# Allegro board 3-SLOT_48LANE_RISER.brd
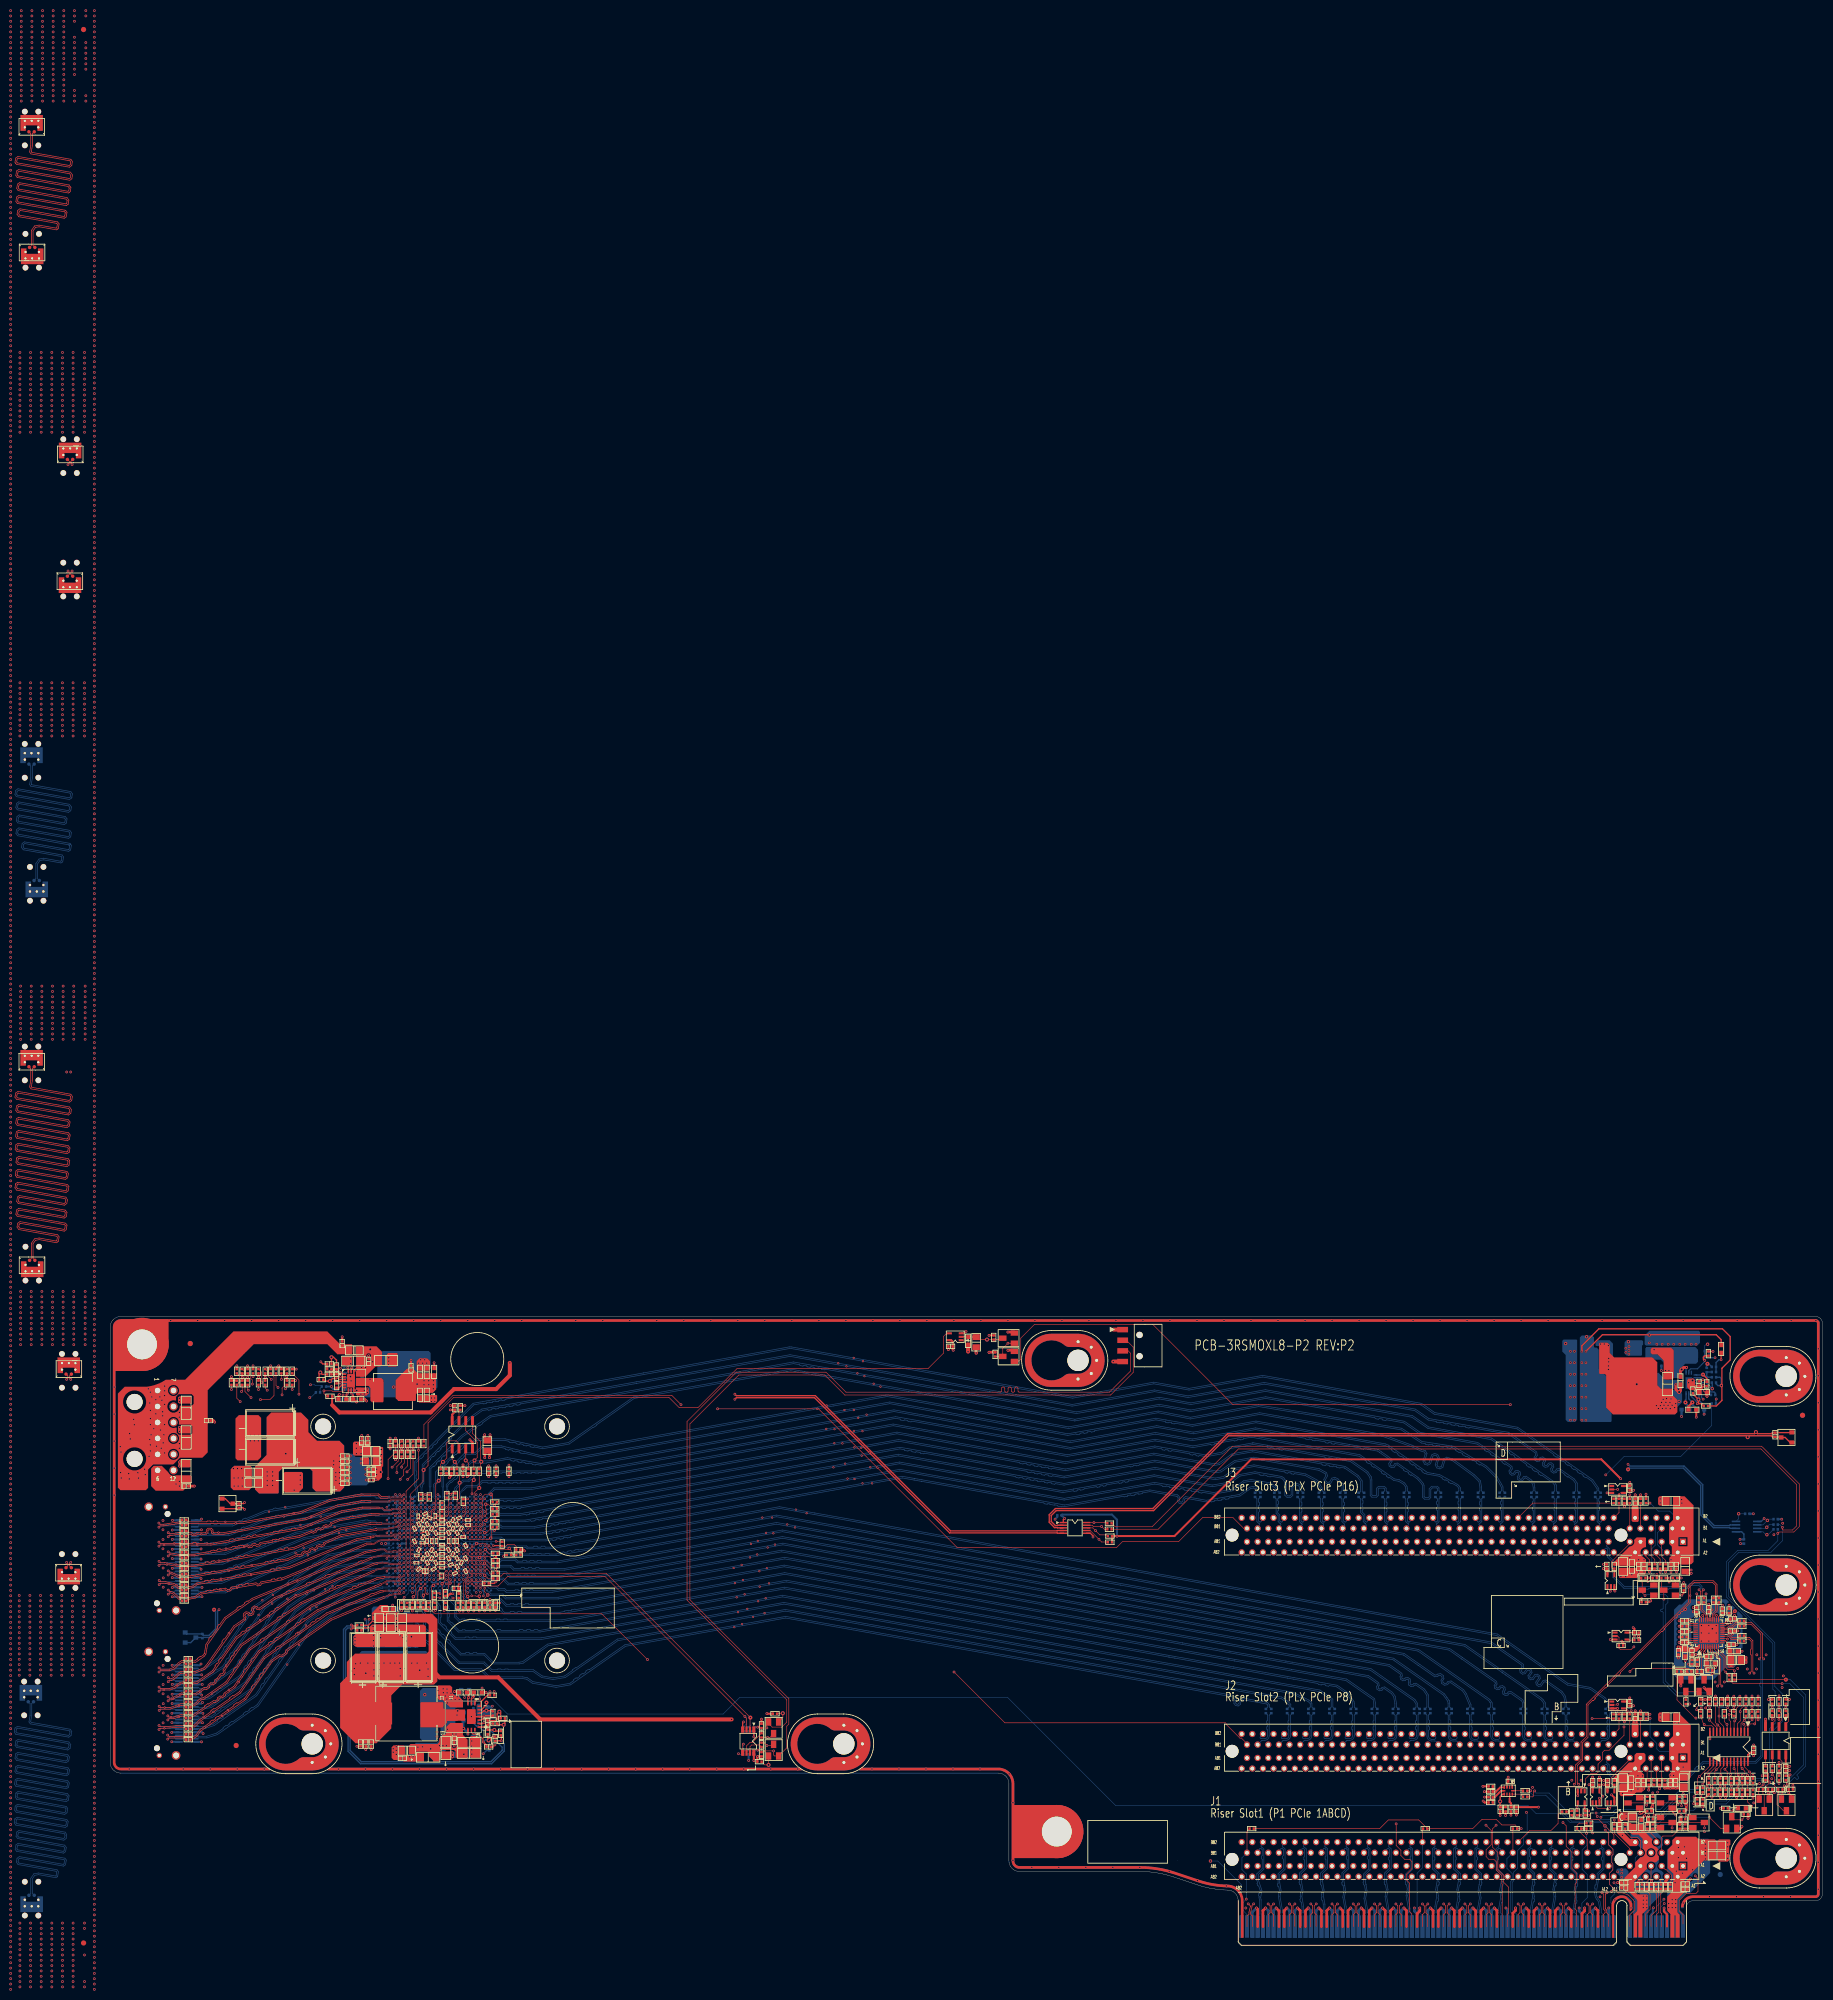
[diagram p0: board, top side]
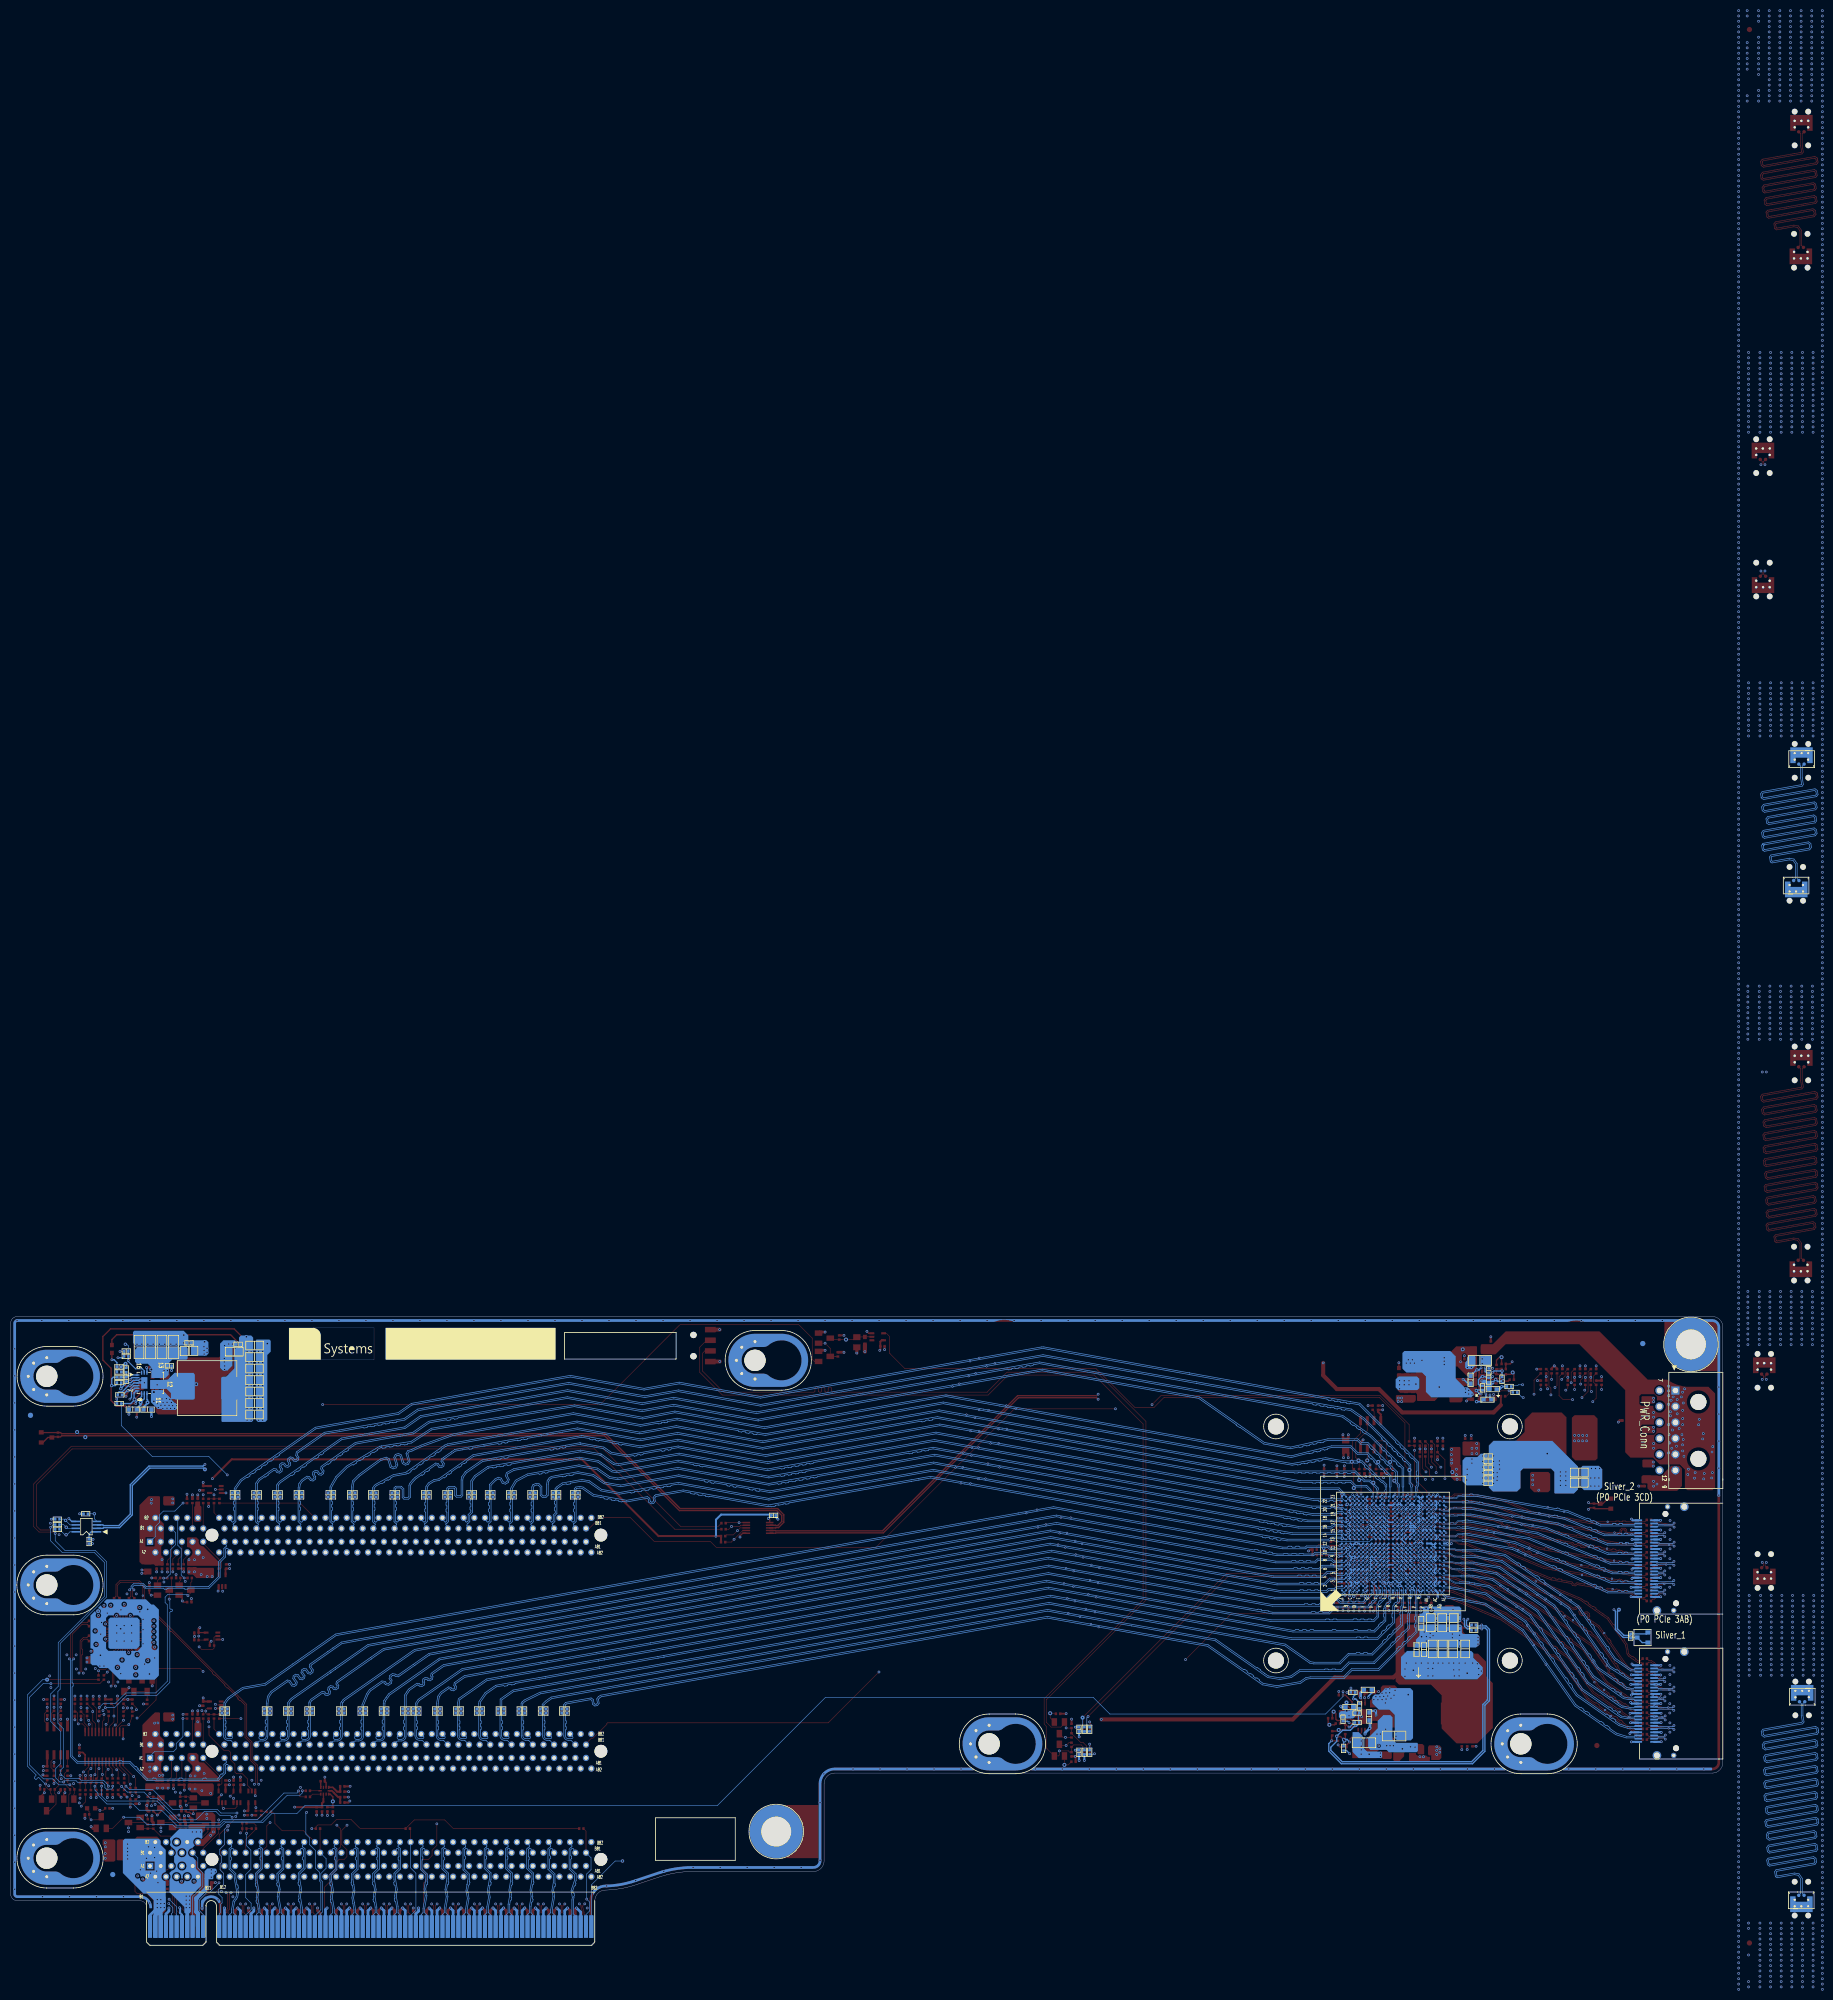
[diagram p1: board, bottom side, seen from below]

Outline 322.05 x 118.24 mm; copper layers: TOP, GND, IN1, VCC, VCC1, IN2, GND1, BOTTOM. Coordinates in mm from the lower left corner of the outline.
Outline path: 0,116.24 0,34.41 0.02,34.15 arc(0.07,33.89) 0.15,33.64 0.27,33.41 0.41,33.19 arc(0.59,32.99) 0.78,32.82 1,32.68 1.23,32.56 1.48,32.48 1.74,32.42 2,32.41 167.05,32.41 167.31,32.39 167.56,32.34 167.81,32.26 168.05,32.14 168.26,31.99 168.46,31.82 168.63,31.63 168.78,31.41 168.89,31.17 168.98,30.93 169.03,30.67 169.05,30.41 169.05,15.91 169.06,15.65 169.11,15.39 169.2,15.14 169.31,14.91 arc(169.46,14.69) 169.63,14.49 169.83,14.32 arc(170.05,14.18) 170.28,14.06 170.53,13.98 170.79,13.92 171.05,13.91 193.68,13.91 194.53,13.89 194.81,13.88 195.38,13.83 195.71,13.8 196.23,13.74 196.58,13.7 197.07,13.62 197.43,13.55 197.91,13.45 198.26,13.37 198.75,13.25 199.09,13.16 199.59,13.01 200,12.88 204.36,11.43 205.18,11.18 206,10.96 206.83,10.78 207.67,10.63 208.51,10.52 209.36,10.45 210.21,10.41 210.49,10.38 arc(210.9,10.27) 211.27,10.07 211.49,9.9 211.69,9.7 211.86,9.47 211.99,9.23 212.09,8.96 212.15,8.69 212.17,8.41 212.17,0.51 212.67,0 282.87,0 283.37,0.51 283.37,7.45 arc(284.33,8.41) 285.28,7.45 285.28,0.51 285.79,0 295.96,0 296.47,0.51 296.47,7.14 arc(296.84,8.04) 297.74,8.41 320.78,8.41 arc(321,8.43) 321.21,8.48 321.41,8.58 321.59,8.7 321.75,8.86 321.88,9.04 arc(321.97,9.24) 322.03,9.46 322.05,9.68 322.05,116.97 322.03,117.2 321.97,117.41 321.88,117.61 321.75,117.79 321.59,117.95 321.41,118.07 321.21,118.17 321,118.23 320.78,118.24 2,118.24 1.74,118.23 1.48,118.18 arc(1.12,118.04) 0.78,117.83 0.59,117.66 0.41,117.46 0.27,117.24 0.15,117.01 0.07,116.76 0.02,116.51 0,116.24

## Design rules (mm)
constraint set DEFAULT: min track width 0.089
net group PWR_VCC: nets P1V8 P3V3
net group VR-G3-VSENSE_S30_VS30: nets P0V9_SENSE_R_N P0V9_SENSE_R_P
net group 50H_W4.5-5.8: nets PEX_EEP_CS_N PEX_EEP_CS_R_N PEX_EEP_SCLK PEX_EEP_SI PEX_EEP_SO PEX_EEP_SO_R RST_PE_SLOT_N RST_PEX_MOS_N
net group CLK-100M_S19-9: nets CLK_100M_PEX8796_DN CLK_100M_PEX8796_DP CLK_100M_PEX8796_R_DN CLK_100M_PEX8796_R_DP CLK_100M_SLOT1_DN CLK_100M_SLOT1_DP CLK_100M_SLOT1_R_DN CLK_100M_SLOT1_R_DP CLK_100M_SLOT2_DN CLK_100M_SLOT2_DP CLK_100M_SLOT2_R_DN CLK_100M_SLOT2_R_DP CLK_100M_SLOT3_DN CLK_100M_SLOT3_DP CLK_100M_SLOT3_R_DN CLK_100M_SLOT3_R_DP
net group DP-85H_W5.3-5.7D6.7-5.3: nets 85OHM_BOT_5INCH_DN 85OHM_BOT_5INCH_DP 85OHM_BOT_10INCH_DN 85OHM_BOT_10INCH_DP 85OHM_L2_5INCH_DN 85OHM_L2_5INCH_DP 85OHM_L2_10INCH_DN 85OHM_L2_10INCH_DP 85OHM_TOP_5INCH_DN 85OHM_TOP_5INCH_DP 85OHM_TOP_10INCH_DN 85OHM_TOP_10INCH_DP PE_SLV_RX_DN<8> PE_SLV_RX_DN<9> PE_SLV_RX_DN<10> PE_SLV_RX_DN<11> PE_SLV_RX_DN<12> PE_SLV_RX_DN<13> PE_SLV_RX_DN<14> PE_SLV_RX_DN<15> PE_SLV_RX_DP<8> PE_SLV_RX_DP<9> PE_SLV_RX_DP<10> PE_SLV_RX_DP<11> PE_SLV_RX_DP<12> PE_SLV_RX_DP<13> PE_SLV_RX_DP<14> PE_SLV_RX_DP<15>
net group JTAG_S10-8_HS-S15-13_VR20/VS30: nets JTAG_R_TCK JTAG_R_TDI JTAG_R_TDO JTAG_R_TMS JTAG_TCK JTAG_TDI JTAG_TDO JTAG_TMS JTAG_TRST_N SLOT2_JTAG_TCK SLOT2_JTAG_TDI SLOT2_JTAG_TDO SLOT2_JTAG_TMS SLOT2_JTAG_TRST_N SLOT3_JTAG_TCK SLOT3_JTAG_TDI SLOT3_JTAG_TDO SLOT3_JTAG_TMS SLOT3_JTAG_TRST_N
net group PCIE-SLOT1-RX_S30-9/S30-15_V9: nets PE_CPU_RX_DN<0> PE_CPU_RX_DN<1> PE_CPU_RX_DN<2> PE_CPU_RX_DN<3> PE_CPU_RX_DN<4> PE_CPU_RX_DN<5> PE_CPU_RX_DN<6> PE_CPU_RX_DN<7> PE_CPU_RX_DN<8> PE_CPU_RX_DN<9> PE_CPU_RX_DN<10> PE_CPU_RX_DN<11> PE_CPU_RX_DN<12> PE_CPU_RX_DN<13> PE_CPU_RX_DN<14> PE_CPU_RX_DN<15> PE_CPU_RX_DP<0> PE_CPU_RX_DP<1> PE_CPU_RX_DP<2> PE_CPU_RX_DP<3> PE_CPU_RX_DP<4> PE_CPU_RX_DP<5> PE_CPU_RX_DP<6> PE_CPU_RX_DP<7> PE_CPU_RX_DP<8> PE_CPU_RX_DP<9> PE_CPU_RX_DP<10> PE_CPU_RX_DP<11> PE_CPU_RX_DP<12> PE_CPU_RX_DP<13> PE_CPU_RX_DP<14> PE_CPU_RX_DP<15> PE_SLOT3_RX_DN<0> PE_SLOT3_RX_DN<1> PE_SLOT3_RX_DN<2> PE_SLOT3_RX_DN<3> PE_SLOT3_RX_DN<4> PE_SLOT3_RX_DN<5> PE_SLOT3_RX_DN<6> PE_SLOT3_RX_DN<7> PE_SLOT3_RX_DN<8> PE_SLOT3_RX_DN<9> PE_SLOT3_RX_DN<10> PE_SLOT3_RX_DN<11> PE_SLOT3_RX_DN<12> PE_SLOT3_RX_DN<13> PE_SLOT3_RX_DN<14> PE_SLOT3_RX_DN<15> PE_SLOT3_RX_DP<0> PE_SLOT3_RX_DP<1> PE_SLOT3_RX_DP<2> PE_SLOT3_RX_DP<3> PE_SLOT3_RX_DP<4> PE_SLOT3_RX_DP<5> PE_SLOT3_RX_DP<6> PE_SLOT3_RX_DP<7> PE_SLOT3_RX_DP<8> PE_SLOT3_RX_DP<9> PE_SLOT3_RX_DP<10> PE_SLOT3_RX_DP<11> PE_SLOT3_RX_DP<12> PE_SLOT3_RX_DP<13> PE_SLOT3_RX_DP<14> PE_SLOT3_RX_DP<15>
net group PCIE-SLOT1-TX_S30-9/S30-15_V9: nets PE_CPU_TX_DN<0> PE_CPU_TX_DN<1> PE_CPU_TX_DN<2> PE_CPU_TX_DN<3> PE_CPU_TX_DN<4> PE_CPU_TX_DN<5> PE_CPU_TX_DN<6> PE_CPU_TX_DN<7> PE_CPU_TX_DN<8> PE_CPU_TX_DN<9> PE_CPU_TX_DN<10> PE_CPU_TX_DP<0> PE_CPU_TX_DP<1> PE_CPU_TX_DP<2> PE_CPU_TX_DP<3> PE_CPU_TX_DP<4> PE_CPU_TX_DP<5> PE_CPU_TX_DP<6> PE_CPU_TX_DP<7> PE_CPU_TX_DP<8> PE_CPU_TX_DP<9> PE_CPU_TX_DP<10> PE_CPU_TX_DP<15> PE_SLOT3_TX_C_DN<0> PE_SLOT3_TX_C_DN<1> PE_SLOT3_TX_C_DN<2> PE_SLOT3_TX_C_DN<3> PE_SLOT3_TX_C_DN<4> PE_SLOT3_TX_C_DN<5> PE_SLOT3_TX_C_DN<6> PE_SLOT3_TX_C_DN<7> PE_SLOT3_TX_C_DN<8> PE_SLOT3_TX_C_DN<9> PE_SLOT3_TX_C_DN<10> PE_SLOT3_TX_C_DN<11> PE_SLOT3_TX_C_DN<12> PE_SLOT3_TX_C_DN<13> PE_SLOT3_TX_C_DN<14> PE_SLOT3_TX_C_DN<15> PE_SLOT3_TX_C_DP<0> PE_SLOT3_TX_C_DP<1> PE_SLOT3_TX_C_DP<2> PE_SLOT3_TX_C_DP<3> PE_SLOT3_TX_C_DP<4> PE_SLOT3_TX_C_DP<5> PE_SLOT3_TX_C_DP<6> PE_SLOT3_TX_C_DP<7> PE_SLOT3_TX_C_DP<8> PE_SLOT3_TX_C_DP<9> PE_SLOT3_TX_C_DP<10> PE_SLOT3_TX_C_DP<11> PE_SLOT3_TX_C_DP<12> PE_SLOT3_TX_C_DP<13> PE_SLOT3_TX_C_DP<14> PE_SLOT3_TX_C_DP<15> PE_SLOT3_TX_DN<0> PE_SLOT3_TX_DN<1> PE_SLOT3_TX_DN<2> PE_SLOT3_TX_DN<3> PE_SLOT3_TX_DN<4> PE_SLOT3_TX_DN<5> PE_SLOT3_TX_DN<6> PE_SLOT3_TX_DN<7> PE_SLOT3_TX_DN<8> PE_SLOT3_TX_DN<9> PE_SLOT3_TX_DN<10> PE_SLOT3_TX_DN<11> PE_SLOT3_TX_DN<12> PE_SLOT3_TX_DN<13> PE_SLOT3_TX_DN<14> PE_SLOT3_TX_DN<15> PE_SLOT3_TX_DP<0> PE_SLOT3_TX_DP<1> PE_SLOT3_TX_DP<2> PE_SLOT3_TX_DP<3> PE_SLOT3_TX_DP<4> PE_SLOT3_TX_DP<5> PE_SLOT3_TX_DP<6> PE_SLOT3_TX_DP<7> PE_SLOT3_TX_DP<8> PE_SLOT3_TX_DP<9> PE_SLOT3_TX_DP<10> PE_SLOT3_TX_DP<11> PE_SLOT3_TX_DP<12> PE_SLOT3_TX_DP<13> PE_SLOT3_TX_DP<14> PE_SLOT3_TX_DP<15>
net group PCIE-SLOT2-RX_S30-9/S30-15_V9: nets PE_SLOT2_RX_DN<0> PE_SLOT2_RX_DN<1> PE_SLOT2_RX_DN<2> PE_SLOT2_RX_DN<3> PE_SLOT2_RX_DN<4> PE_SLOT2_RX_DN<5> PE_SLOT2_RX_DN<6> PE_SLOT2_RX_DN<7> PE_SLOT2_RX_DN<8> PE_SLOT2_RX_DN<9> PE_SLOT2_RX_DN<10> PE_SLOT2_RX_DN<11> PE_SLOT2_RX_DN<12> PE_SLOT2_RX_DN<13> PE_SLOT2_RX_DN<14> PE_SLOT2_RX_DN<15> PE_SLOT2_RX_DP<0> PE_SLOT2_RX_DP<1> PE_SLOT2_RX_DP<2> PE_SLOT2_RX_DP<3> PE_SLOT2_RX_DP<4> PE_SLOT2_RX_DP<5> PE_SLOT2_RX_DP<6> PE_SLOT2_RX_DP<7> PE_SLOT2_RX_DP<8> PE_SLOT2_RX_DP<9> PE_SLOT2_RX_DP<10> PE_SLOT2_RX_DP<11> PE_SLOT2_RX_DP<12> PE_SLOT2_RX_DP<13> PE_SLOT2_RX_DP<14> PE_SLOT2_RX_DP<15>
net group PCIE-SLOT2-TX_S30-9/S30-15_V9: nets PE_SLOT2_TX_C_DN<0> PE_SLOT2_TX_C_DN<1> PE_SLOT2_TX_C_DN<2> PE_SLOT2_TX_C_DN<3> PE_SLOT2_TX_C_DN<4> PE_SLOT2_TX_C_DN<5> PE_SLOT2_TX_C_DN<6> PE_SLOT2_TX_C_DN<7> PE_SLOT2_TX_C_DN<8> PE_SLOT2_TX_C_DN<9> PE_SLOT2_TX_C_DN<10> PE_SLOT2_TX_C_DN<11> PE_SLOT2_TX_C_DN<12> PE_SLOT2_TX_C_DN<13> PE_SLOT2_TX_C_DN<14> PE_SLOT2_TX_C_DN<15> PE_SLOT2_TX_C_DP<0> PE_SLOT2_TX_C_DP<1> PE_SLOT2_TX_C_DP<2> PE_SLOT2_TX_C_DP<3> PE_SLOT2_TX_C_DP<4> PE_SLOT2_TX_C_DP<5> PE_SLOT2_TX_C_DP<6> PE_SLOT2_TX_C_DP<7> PE_SLOT2_TX_C_DP<8> PE_SLOT2_TX_C_DP<9> PE_SLOT2_TX_C_DP<10> PE_SLOT2_TX_C_DP<11> PE_SLOT2_TX_C_DP<12> PE_SLOT2_TX_C_DP<13> PE_SLOT2_TX_C_DP<14> PE_SLOT2_TX_C_DP<15> PE_SLOT2_TX_DN<0> PE_SLOT2_TX_DN<1> PE_SLOT2_TX_DN<2> PE_SLOT2_TX_DN<3> PE_SLOT2_TX_DN<4> PE_SLOT2_TX_DN<5> PE_SLOT2_TX_DN<6> PE_SLOT2_TX_DN<7> PE_SLOT2_TX_DN<8> PE_SLOT2_TX_DN<9> PE_SLOT2_TX_DN<10> PE_SLOT2_TX_DN<11> PE_SLOT2_TX_DN<12> PE_SLOT2_TX_DN<13> PE_SLOT2_TX_DN<14> PE_SLOT2_TX_DN<15> PE_SLOT2_TX_DP<0> PE_SLOT2_TX_DP<1> PE_SLOT2_TX_DP<2> PE_SLOT2_TX_DP<3> PE_SLOT2_TX_DP<4> PE_SLOT2_TX_DP<5> PE_SLOT2_TX_DP<6> PE_SLOT2_TX_DP<7> PE_SLOT2_TX_DP<8> PE_SLOT2_TX_DP<9> PE_SLOT2_TX_DP<10> PE_SLOT2_TX_DP<11> PE_SLOT2_TX_DP<12> PE_SLOT2_TX_DP<13> PE_SLOT2_TX_DP<14> PE_SLOT2_TX_DP<15>
net group PE_J7-J8_TX: nets PE_SLV_TX_DN<0> PE_SLV_TX_DN<1> PE_SLV_TX_DN<2> PE_SLV_TX_DN<3> PE_SLV_TX_DN<4> PE_SLV_TX_DN<5> PE_SLV_TX_DN<6> PE_SLV_TX_DN<7> PE_SLV_TX_DP<0> PE_SLV_TX_DP<1> PE_SLV_TX_DP<2> PE_SLV_TX_DP<3> PE_SLV_TX_DP<4> PE_SLV_TX_DP<5> PE_SLV_TX_DP<6> PE_SLV_TX_DP<7> PE_SLV_TX_DP<15>
net group PWR2: nets GND
net group PWR-20: nets VR_P0V9_BT VR_P1V8_BT VR_P3V3_BT
net group PWR_S10: nets CLK_BUF_HIBW_BYPM_LOBW_N I2C_SC6_2N7002_G_SCL I2C_SD6_2N7002_G_SDA I2C_SLOT2_2N7002_G_SCL I2C_SLOT2_2N7002_G_SDA I2C_SLOT3_2N7002_G_SCL I2C_SLOT3_2N7002_G_SDA P0V9_VREF P1V8_FB P1V8_FB_RC P3V3_FB P3V3_FB_RC P3V3_RT P12V P12V_MB P12V_PSU
net group PWR_W30: nets P0V9 P0V9_A P0V9_RT P0V9_VCC P0V9_VIN P1V8_A P1V8_AGND P1V8_RT P1V8_SS P1V8_VCC P1V8_VIN P3V3_AGND P3V3_BUF_VDDA P3V3_BUF_VDDR P3V3_CLK_BUF_VDD P3V3_MB P3V3_STBY_MB P3V3_VCC P3V3_VIN VR_P0V9_SW VR_P1V8_PVIN VR_P3V3_SW
net group RESET_S10-8_HS-S15-13_VR20/VS30: nets P3V3_PG
net group SMB-50H_W4.5-5.8: nets I2C_PCA9548_SC3_SLOT2_SCL I2C_PCA9548_SC5_3V3_PE_SCL I2C_PCA9548_SC5_P1V8_SCL I2C_PCA9548_SC5_PE_SCL I2C_PCA9548_SC6_3V3_CLK_SCL I2C_PCA9548_SC6_CLK_SCL I2C_PCA9548_SD3_SLOT2_SDA I2C_PCA9548_SD5_3V3_PE_SDA I2C_PCA9548_SD5_P1V8_SDA I2C_PCA9548_SD5_PE_SDA I2C_PCA9548_SD6_3V3_CLK_SDA I2C_PCA9548_SD6_CLK_SDA I2C_PE_SCL_R I2C_PE_SDA_R I2C_SC5_2N7002_G_SCL I2C_SD5_2N7002_G_SDA I2C_SLOT1_2N7002_G_SCL I2C_SLOT1_2N7002_G_SDA I2C_SLOT1_3V3_SCL I2C_SLOT1_3V3_SDA I2C_SLOT2_3V3_SCL I2C_SLOT2_3V3_SDA I2C_SLOT3_3V3_SCL I2C_SLOT3_3V3_SDA
net group SPI: nets PEX_EEP_HOLD_N
net group VR-G2-VCC_S20V20/S30_VS30: nets VR_P3V3_PVIN
net group VR-NOISY_S20/S30_VS30: nets VR_P1V8_SW
net group VR-SEN-S5/30: nets P0V9_AGND P0V9_COMP P0V9_COMP_RC P0V9_FB P0V9_FB_RC P0V9_VSNS P1V8_COMP P1V8_COMP_RC P1V8_VSENSE_R P3V3_COMP P3V3_COMP_RC P3V3_SENSE_R P3V3_VREF P3V3_VSNS
net group VR_SEN: nets THER_SEN1_DN_1 THER_SEN1_DN_2 THER_SEN1_DP_1 THER_SEN1_DP_2 THER_SEN2_DN THER_SEN2_DP

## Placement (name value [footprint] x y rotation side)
C1  -  [C0402]  64.85 101.09 90 top
C2  -  [C0201]  57.25 78.37 112.5 top
C3  -  [C0402]  66.37 89.15 90 top
C4  -  [C0201]  57.25 75.97 112.5 top
C5  -  [C0201]  59.25 81.16 22.5 top
C6  -  [C0201]  58.05 74.37 247.5 top
C7  -  [C0201]  58.85 78.37 67.5 top
C8  -  [C0402]  72.59 89.15 90 top
C9  -  [C0201]  59.65 79.17 292.5 top
C10  -  [C0201]  65.25 72.76 112.5 top
C11  -  [C0402]  44.15 89.92 0 top
C12  -  [C0402]  75.01 89.15 90 top
C13  -  [C0402]  44.15 88.9 0 top
C14  -  [C0201]  65.25 74.36 112.5 top
C15  -  [C0201]  58.85 72.76 67.5 top
C16  -  [C0201]  62.45 79.17 180 top
C17  -  [C0201]  58.05 79.16 112.5 top
C18  -  [C0201]  64.46 73.56 247.5 top
C19  -  [C0201]  66.06 71.96 247.5 top
C20  -  [C0201]  64.45 78.37 67.5 top
C21  -  [C0201]  66.86 72.77 292.5 top
C22  -  [C0201]  61.25 79.17 292.5 top
C23  -  [C0402]  14.68 38.69 180 top
C24  -  [C0402]  14.68 40.72 180 top
C25  -  [C0402]  14.68 42.75 180 top
C26  -  [C0402]  14.68 44.78 180 top
C27  -  [C0402]  281.26 44.07 270 bottom
C28  -  [C0402]  273.3 44.07 270 bottom
C29  -  [C0402]  269.3 44.07 270 bottom
C30  -  [C0402]  265.3 44.07 270 bottom
C31  -  [C0402]  282.28 44.07 270 bottom
C32  -  [C0402]  274.31 44.07 270 bottom
C33  -  [C0402]  270.31 44.07 270 bottom
C34  -  [C0402]  266.31 44.07 270 bottom
C35  -  [C0402]  14.68 39.7 180 top
C36  -  [C0402]  14.68 41.74 180 top
C37  -  [C0402]  14.68 43.77 180 top
C38  -  [C0402]  14.68 45.8 180 top
C39  -  [C0402]  280.34 84.71 270 bottom
C40  -  [C0402]  276.3 84.71 270 bottom
C41  -  [C0402]  272.37 84.71 270 bottom
C42  -  [C0402]  268.33 84.71 270 bottom
C43  -  [C0402]  279.33 84.71 270 bottom
C44  -  [C0402]  275.29 84.71 270 bottom
C45  -  [C0402]  271.35 84.71 270 bottom
C46  -  [C0402]  267.31 84.71 270 bottom
C47  -  [C0805]  49.1 91.06 180 top
C48  -  [C0805]  70.94 93.98 90 top
C49  -  [C0402]  49.1 89.53 180 top
C50  -  [C0402]  47.32 94.87 90 top
C51  -  [C0402]  49.1 88.52 180 top
C52  -  [C0402]  48.46 94.87 90 top
C53  -  [C0201#2]  62.33 69.44 270 top
C54  -  [C0201#2]  49.1 87.5 180 top
C55  -  [C0402]  259.3 44.07 270 bottom
C56  -  [C0402]  255.3 44.07 270 bottom
C57  -  [C0402]  251.3 44.07 270 bottom
C58  -  [C0402]  247.3 44.07 270 bottom
C59  -  [C0402]  245.26 44.07 270 bottom
C60  -  [C0402]  241.28 44.07 270 bottom
C61  -  [C0402]  237.31 44.07 270 bottom
C62  -  [C0402]  233.35 44.07 270 bottom
C63  -  [C0402]  229.31 44.07 270 bottom
C64  -  [C0402]  225.38 44.07 270 bottom
C65  -  [C0402]  221.38 44.07 270 bottom
C66  -  [C0402]  217.38 44.07 270 bottom
C67  -  [C0402]  260.31 44.07 270 bottom
C68  -  [C0402]  256.31 44.07 270 bottom
C69  -  [C0402]  252.31 44.07 270 bottom
C70  -  [C0402]  248.31 44.07 270 bottom
C71  -  [C0402]  246.28 44.07 270 bottom
C72  -  [C0402]  242.29 44.07 270 bottom
C73  -  [C0402]  238.33 44.07 270 bottom
C74  -  [C0402]  234.37 44.07 270 bottom
C75  -  [C0402]  230.33 44.07 270 bottom
C76  -  [C0402]  226.39 44.07 270 bottom
C77  -  [C0402]  222.39 44.07 270 bottom
C78  -  [C0402]  218.39 44.07 270 bottom
C79  -  [C0402]  14.68 46.82 180 top
C80  -  [C0402]  14.68 48.85 180 top
C81  -  [C0402]  14.68 50.88 180 top
C82  -  [C0402]  14.68 52.91 180 top
C83  -  [C0402]  13.92 64.76 180 top
C84  -  [C0402]  13.92 66.8 180 top
C85  -  [C0402]  13.92 68.83 180 top
C86  -  [C0402]  13.92 70.86 180 top
C87  -  [C0402]  13.92 72.89 180 top
C88  -  [C0402]  13.92 74.92 180 top
C89  -  [C0402]  13.92 76.96 180 top
C90  -  [C0402]  13.92 78.99 180 top
C91  -  [C0402]  14.68 47.83 180 top
C92  -  [C0402]  14.68 49.86 180 top
C93  -  [C0402]  14.68 51.9 180 top
C94  -  [C0402]  14.68 53.93 180 top
C95  -  [C0402]  13.92 65.78 180 top
C96  -  [C0402]  13.92 67.81 180 top
C97  -  [C0402]  13.92 69.84 180 top
C98  -  [C0402]  13.92 71.88 180 top
C99  -  [C0402]  13.92 73.91 180 top
C100  -  [C0402]  13.92 75.94 180 top
C101  -  [C0402]  13.92 77.97 180 top
C102  -  [C0402]  13.92 80 180 top
C103  -  [C0402]  262.33 84.71 270 bottom
C104  -  [C0402]  258.29 84.71 270 bottom
C105  -  [C0402]  254.33 84.71 270 bottom
C106  -  [C0402]  250.29 84.71 270 bottom
C107  -  [C0402]  244.36 84.71 270 bottom
C108  -  [C0402]  240.36 84.71 270 bottom
C109  -  [C0402]  235.85 84.71 270 bottom
C110  -  [C0402]  232.36 84.71 270 bottom
C111  -  [C0402]  228.36 84.71 270 bottom
C112  -  [C0402]  224.36 84.71 270 bottom
C113  -  [C0402]  219.98 84.71 270 bottom
C114  -  [C0402]  216.36 84.71 270 bottom
C115  -  [C0402]  261.32 84.71 270 bottom
C116  -  [C0402]  257.28 84.71 270 bottom
C117  -  [C0402]  253.32 84.71 270 bottom
C118  -  [C0402]  249.28 84.71 270 bottom
C119  -  [C0402]  243.34 84.71 270 bottom
C120  -  [C0402]  239.34 84.71 270 bottom
C121  -  [C0402]  234.84 84.71 270 bottom
C122  -  [C0402]  231.34 84.71 270 bottom
C123  -  [C0402]  227.34 84.71 270 bottom
C124  -  [C0402]  223.34 84.71 270 bottom
C125  -  [C0402]  218.96 84.71 270 bottom
C126  -  [C0402]  215.34 84.71 270 bottom
C127  -  [C0402]  52.66 94.36 270 top
C128  -  [C0201]  58.05 70.77 225 top
C129  -  [C0201]  58.73 75.74 0 top
C130  -  [C0201]  57.66 73.33 180 top
C131  -  [C0201]  61.16 80.77 270 top
C132  -  [C0201]  64.05 71.56 22.5 top
C133  -  [C0201]  65.26 71.17 292.5 top
C134  -  [C0201]  58.85 76.77 67.5 top
C135  -  [C0201]  58.96 70.36 270 top
C136  -  [C0201]  60.05 80.36 157.5 top
C137  -  [C0201]  65.65 80.36 22.5 top
C138  -  [C0201]  64.45 79.97 67.5 top
C139  -  [C0201]  58.85 79.97 247.5 top
C140  -  [C0201]  65.25 77.56 112.5 top
C141  -  [C0201]  66.86 75.17 292.5 top
C142  -  [C0201]  64.86 69.96 202.5 top
C143  -  [C0201]  66.4 76.77 0 top
C144  -  [C0201]  65.26 79.17 292.5 top
C145  -  [C0402]  71.45 64.01 270 top
C146  -  [C0201]  66.05 78.37 67.5 top
C147  -  [C0402]  72.47 64.01 270 top
C148  -  [C0201]  66.86 70.37 292.5 top
C149  -  [C0402]  44.15 91.01 0 top
C150  -  [C0201]  57.61 71.96 180 top
C151  -  [C0201]  67.32 80 0 top
C152  -  [C0805]  295.99 30.61 270 top
C153  -  [C0402]  293.45 30.61 270 top
C154  -  [C0402]  294.46 30.61 270 top
C155  -  [C0603]  286.08 30.61 270 top
C156  -  [C0402]  287.35 30.61 270 top
C157  -  [C0402]  288.37 30.61 270 top
C158  -  [C0402]  286.84 43.05 90 top
C159  -  [C0402]  277.45 24.89 270 top
C160  -  [C0402]  71.2 89.15 90 top
C161  -  [C0201]  67.34 79.04 0 top
C162  -  [C0201]  57.95 80.67 270 top
C163  -  [C0201]  62.45 71.04 180 top
C164  -  [C0201]  60.85 70.76 208.4 top
C165  -  [TAJ_D_7-3X4-3]  52.88 54.2 90 top
C166  -  [TAJ_D_7-3X4-3]  30.05 98.17 180 top
C167  -  [TAJ_D_7-3X4-3]  30.05 92.84 180 top
C168  -  [C0805]  302.21 18.8 0 top
C169  -  [C0805]  286.34 23.24 90 top
C170  -  [TAJ_D_7-3X4-3]  58.12 54.23 90 top
C171  -  [TAJ_D_7-3X4-3]  37.03 87.38 180 top
C172  -  [C0402]  278.84 30.61 90 top
C173  -  [TAJ_D_7-3X4-3]  47.68 54.2 90 top
C174  -  [C0402]  47.09 37.85 270 top
C175  -  [C0402]  44.15 86.87 0 bottom
C176  -  [C0402]  48.08 37.85 270 top
C177  -  [C0402]  44.15 86.87 0 top
C178  -  [C0402]  263.48 25.6 270 top
C179  -  [C0402]  264.49 25.6 270 top
C180  -  [C0402]  261.44 25.6 270 top
C181  -  [C0201]  65.28 76.02 90 top
C182  -  [C0402]  44.15 87.88 0 bottom
C183  -  [C0402]  44.15 89.92 0 bottom
C184  -  [C0402]  44.15 87.88 0 top
C185  -  [C0402]  44.15 91.01 0 bottom
C186  -  [C0402]  44.15 88.9 0 bottom
C187  -  [C0402]  44.15 92.02 0 bottom
C188  -  [C0402]  44.15 92.02 0 top
C189  -  [C0402]  259.67 27.89 180 top
C190  -  [C0402]  259.67 28.91 180 top
C191  -  [C0402]  158.07 112.65 180 top
C192  -  [C0603]  161.37 113.67 270 top
C193  -  [C0805]  162.89 113.41 270 top
C194  -  [C0201]  59.54 70.36 270 top
C215  -  [C0603]  305.39 55.32 0 top
C216  -  [C0402]  296.12 59 180 top
C217  -  [C0402]  304.88 56.59 0 top
C218  -  [C0402]  300.68 63.12 90 top
C219  -  [C0402]  298.42 63.12 90 top
C220  -  [C0402]  296.12 56.97 180 top
C221  -  [C0402]  296.12 61.03 180 top
C222  -  [C0402]  303.22 62.87 90 top
C223  -  [C0402]  309.12 36.68 90 top
C224  -  [C0603]  296.25 55.07 270 top
C225  -  [C0402]  297.52 55.07 270 top
C226  -  [C0603]  301.07 53.03 0 top
C227  -  [C0402]  300.69 54.3 0 top
C242  -  [C0805]  296.24 71.25 270 top
C243  -  [C0402]  294.59 71.25 270 top
C244  -  [C0402]  293.57 71.25 270 top
C245  -  [C0603]  286.21 71.25 270 top
C246  -  [C0402]  288.49 71.25 270 top
C247  -  [C0402]  287.48 71.25 270 top
C248  -  [C0402]  286.84 83.57 90 top
C249  -  [C0805]  302.21 16.89 0 top
C250  -  [C0402]  296.24 11.56 0 top
C251  -  [C0402]  296.24 10.54 0 top
C252  -  [C0603]  287.99 22.86 90 top
C253  -  [C0402]  284.68 10.79 180 top
C254  -  [C0402]  284.68 11.81 180 top
C255  -  [C0402]  283.92 22.35 90 top
C257  -  [C0402]  305.14 61.39 0 top
C258  -  [C0402]  305.14 59.13 0 top
C259  -  [C0402]  307.29 75.95 270 bottom
C260  -  [C0402]  17.35 58.17 90 bottom
C265  -  [C0402]  178.54 80.87 180 bottom
C269  -  [C0201]  61.25 77.57 292.5 top
C271  -  [C0201]  61.25 73.57 292.5 top
C273  -  [C0201]  61.25 71.97 292.5 top
C275  -  [C0201]  63.66 77.57 292.5 top
C277  -  [C0201]  63.65 72.76 112.5 top
C279  -  [C0201]  60.45 74.36 67.5 top
C281  -  [C0201]  60.45 72.76 67.5 top
C283  -  [C0201]  62.45 77.44 180 top
C287  -  [C0201]  62.45 71.91 180 top
C290  -  [C0201]  62.45 72.77 0 top
C294  -  [C0201]  62.45 74.5 0 top
C297  -  [C0201]  62.45 73.63 180 top
C352  -  [C0402]  287.1 58.8 0 top
C386  -  [C0201]  59.65 71.96 292.5 top
C390  -  [C0201]  59.65 77.57 292.5 top
C394  -  [C0201]  62.45 75.36 180 top
C398  -  [C0201]  60.45 78.37 67.5 top
C402  -  [C0201]  62.45 76.58 0 top
C406  -  [C0201]  62.45 80.01 180 top
C410  -  [C0201]  62.45 78.31 0 top
C414  -  [C0201]  64.55 76.02 90 top
C418  -  [C0201]  63.65 74.36 112.5 top
C422  -  [C0201]  59.6 76.02 270 top
C426  -  [C0201]  60.49 76.02 90 top
C430  -  [C0201]  61.38 76.02 270 top
C434  -  [C0201]  63.67 76.02 270 top
C438  -  [C0201]  63.66 79.17 292.5 top
C442  -  [C0201]  59.65 73.57 292.5 top
C450  -  [C0402]  121.11 36.32 90 bottom
C451  -  [C0402]  121.11 40.64 90 bottom
C452  -  [C0402]  315.16 33.27 270 top
C455  -  [C0402]  281.51 71.25 90 top
C456  -  [C0402]  281.64 30.61 90 top
C460  -  [C0402]  285.83 85.98 270 top
C461  -  [C0402]  285.83 45.47 270 top
C463  -  [C1206]  14.3 101.09 90 top
C464  -  [C1206]  14.3 95.5 90 top
C465  -  [C0402]  18.49 98.68 0 top
C466  -  [C1206]  14.3 89.15 90 top
C467  -  [C0402]  14.3 86.36 0 top
C468  -  [C0402]  313.13 96.01 90 top
C469  -  [C0402]  24.23 82.68 270 top
C477  -  [C0805]  293.57 83.57 180 top
C478  -  [C0805]  284.56 71.25 270 top
C479  -  [C0805]  293.57 42.93 180 top
C480  -  [C0805]  284.56 30.61 270 top
CON1  -  [HEADER1X4S2NH_P2H2_RA]  193.63 112.78 270 top
D1  -  [LED0603]  306.91 25.78 0 top
H1  -  [HOLE_C10D5-6B10_NPB_H11_STANDOFF]  6 113 180 bottom
J1  -  [PCIE_X16D_H11]  295.83 14.93 270 top
J2  -  [PCIE_X16D_H11]  295.83 35.25 270 top
J3  -  [PCIE_X16D_H11]  295.83 75.89 270 top
J5  -  [GF_PCIE_X16]  284.33 7.45 180 bottom
J6  -  [PWR2X6D2NH_P3W3H8-9_RA]  8.92 104.32 90 bottom
J7  -  [SLIVER_X8_RA]  7.84 45.5 90 bottom
J8  -  [SLIVER_X8_RA]  7.84 72.75 90 bottom
L1  -  [B2012]  305.77 53.67 0 top
L2  -  [B2012]  49.1 92.96 180 top
L3  -  [B2012]  27 88.9 0 top
L4  -  [B2012]  27 87 0 top
L5  -  [B2012]  27 87 0 bottom
L6  -  [B2012]  27 88.9 0 bottom
ME1  -  [LABEL20X4_SST21X5]  217.88 110.24 180 bottom
ME4  -  [LABEL_32X6_FULL]  251.54 110.11 180 bottom
ME5  -  [ZT_LOG_6X16]  269.7 110.11 180 bottom
MH1  -  [HOLE_D3N_PKO10]  40.05 53.56 0 top
MH2  -  [HOLE_D3N_PKO10]  84.06 53.56 0 top
MH3  -  [HOLE_D3N_PKO10]  84.05 97.57 0 top
MH4  -  [HOLE_D3N_PKO10]  40.05 97.57 0 top
MH5  -  [GND_C10D4_6-5B10_OB5]  138 37.9 270 top
MH6  -  [GND_C10D4_6-5B10_OB5]  315.25 16.41 270 top
MH7  -  [GND_C10D4_6-5B10_OB5]  315.25 67.77 270 top
MH8  -  [HOLE_C10D5-6B10_NPB_H11_STANDOFF]  178.05 21.41 180 bottom
MH9  -  [GND_C10D4_6-5B10_OB5]  182.05 110 270 top
MH10  -  [GND_C10D4_6-5B10_OB5]  38 37.9 270 top
MH11  -  [GND_C10D4_6-5B10_OB5]  315.25 107 270 top
NOREF  -  []  10.85 42.78 90 top
NOREF#2  -  []  9.2 51.79 90 top
NOREF#3  -  []  278.33 7.8 0 top
NOREF#4  -  [unnamed#2]  -5 360.19 0 top
NOREF#5  -  []  234.32 7.8 0 top
NOREF#6  -  []  10.92 66.43 90 top
NOREF#7  -  [unnamed#2]  23.7 37.59 0 top
NOREF#8  -  []  299.29 66.86 0 top
NOREF#9  -  []  9.2 71.84 90 top
NOREF#10  -  []  238.33 7.8 0 top
NOREF#11  -  []  10.92 70.03 90 top
NOREF#12  -  []  226.34 7.8 0 top
NOREF#13  -  []  10.92 49.97 90 top
NOREF#14  -  []  214.61 7.8 0 top
NOREF#15  -  []  230.33 7.8 0 top
NOREF#16  -  []  273.33 7.8 0 top
NOREF#17  -  []  275.79 30.3 180 top
NOREF#18  -  []  10.92 73.61 90 top
NOREF#19  -  []  9.22 68.23 90 top
NOREF#20  -  [unnamed#2]  318.31 99.67 0 top
NOREF#21  -  []  10.9 46.36 90 top
NOREF#22  -  []  269.34 7.8 0 top
NOREF#23  -  []  251.33 7.8 0 top
NOREF#24  -  []  9.2 48.19 90 top
NOREF#25  -  []  259.34 7.8 0 top
NOREF#26  -  [unnamed#2]  15.06 113.16 0 top
NOREF#27  -  []  247.32 7.8 0 top
NOREF#28  -  []  218.31 7.8 0 top
NOREF#29  -  []  10.92 77.22 90 top
NOREF#30  -  []  265.33 7.8 0 top
NOREF#31  -  []  9.22 44.58 90 top
NOREF#32  -  []  9.17 75.44 90 top
NOREF#33  -  []  9.17 79.02 90 top
NOREF#34  -  []  9.2 40.97 90 top
NOREF#35  -  []  302.74 48.77 180 top
NOREF#36  -  []  10.82 39.17 90 top
NOREF#37  -  []  222.33 7.8 0 top
NOREF#38  -  []  255.32 7.8 0 top
NOREF#39  -  []  308.79 51.21 180 top
NOREF#40  -  []  310.59 53.87 180 top
NOREF#41  -  [unnamed#2]  -5 0.47 0 top
NOREF#42  -  [unnamed#2]  183.9 15.47 0 top
NOREF#43  -  []  18.67 -76.43 0 top
NOREF#44  -  []  242.34 7.8 0 top
NOREF#45  -  [unnamed#2]  302.85 13.34 180 bottom
NOREF#46  -  [unnamed#2]  15.06 113.16 180 bottom
NOREF#47  -  [unnamed#2]  318.31 99.67 180 bottom
NOREF#48  -  [unnamed#2]  200.74 16 180 bottom
PC506  -  [C0402]  300.31 111.74 0 bottom
PC508  -  [C0603]  296.3 100.75 0 bottom
PC509  -  [C0402]  298.84 105.65 270 top
PC510  -  [C0603]  299.07 100.75 0 bottom
PC511  -  [C0402]  292.18 108.97 180 bottom
PC514  -  [C0603]  295.36 106.18 270 top
PC515  -  [C1206]  293.57 112.52 90 bottom
PC516  -  [C0402]  300.3 106.43 90 bottom
PC517  -  [C1206]  292.94 105.54 270 top
PC518  -  [C0402]  301.66 106.82 180 bottom
PC519  -  [C1206]  297.89 112.52 90 bottom
PC520  -  [C1206]  295.73 112.52 90 bottom
PC521  -  [C1206]  291.42 112.52 90 bottom
PC522  -  [C0402]  279.26 113.03 0 bottom
PC524  -  [C0805]  276.18 110.62 180 bottom
PC526  -  [C0805]  276.18 106.3 180 bottom
PC527  -  [C0402]  301.65 108.77 0 bottom
PC529  -  [C0805]  276.18 108.46 180 bottom
PC530  -  [C0805]  276.18 112.78 180 bottom
PC531  -  [C0805]  276.18 104.14 180 bottom
PC532  -  [C0402]  288.49 113.28 0 bottom
PC533  -  [C0805]  279.99 111.63 0 bottom
PC539  -  [C0402]  44.02 108.05 90 bottom
PC541  -  [C0603]  46.45 102.7 0 top
PC542  -  [C0603]  43.69 102.7 180 top
PC543  -  [C0402]  48.62 109.8 90 top
PC545  -  [C1206]  51.89 109.98 0 top
PC546  -  [C0603]  47.45 106.33 270 bottom
PC547  -  [C0402]  42.58 106.99 90 top
PC548  -  [C1206]  45.74 109.87 180 top
PC549  -  [C0402]  41.22 107.37 0 top
PC550  -  [C1206]  45.7 109.98 180 bottom
PC551  -  [C0402]  56.59 108.58 90 top
PC552  -  [C0603]  59.54 107.82 90 top
PC553  -  [C0402]  43.64 113.16 90 top
PC554  -  [C0603]  59.54 103.5 270 top
PC555  -  [C0402]  41.23 109.33 180 top
PC556  -  [C0603]  58.27 103.5 270 top
PC557  -  [C0603]  58.27 107.82 90 top
PC580  -  [C0402]  71.2 37.32 0 top
PC581  -  [C0603]  66.38 47.57 0 top
PC582  -  [C0402]  71.45 42.55 90 bottom
PC583  -  [C0603]  69.15 47.57 0 top
PC584  -  [C0402]  64.71 38.57 270 top
PC585  -  [C1206]  67.55 36.11 0 top
PC586  -  [C1206]  59.83 35.37 180 top
PC587  -  [C0603]  66.52 43.05 90 bottom
PC588  -  [C1206]  67.51 38.1 0 bottom
PC589  -  [C0402]  71.02 41.88 270 top
PC591  -  [C0402]  72.4 41.72 180 top
PC592  -  [C0402]  49.1 37.85 270 top
PC593  -  [C0402]  54.95 35.19 0 top
PC594  -  [C0805]  54.56 55.75 90 bottom
PC595  -  [C0805]  50.62 60.71 270 bottom
PC596  -  [C0805]  52.78 60.71 270 bottom
PC597  -  [C0402]  72.4 38.87 270 top
PC598  -  [C0805]  52.78 60.71 270 top
PC599  -  [C0805]  50.62 60.71 270 top
PC600  -  [C0805]  54.94 60.71 270 bottom
PC788  -  [C1206]  61.8 39.37 180 bottom
PC1531  -  [C0805]  276.18 99.82 180 bottom
PC1533  -  [C0805]  276.18 101.98 180 bottom
PC1588  -  [C1206]  63.16 37.13 270 top
PC1589  -  [C1206]  67.55 38.18 0 top
PC1592  -  [C0603]  56.21 55.63 90 bottom
PC1594  -  [C0603]  56.72 60.58 270 bottom
PC1595  -  [C0603]  52.4 63.25 0 top
PC1596  -  [C0805]  48.46 55.75 90 bottom
PC1598  -  [C0805]  50.75 55.75 90 bottom
PC1599  -  [C0805]  52.66 55.75 90 bottom
PC1600  -  [C0805]  54.92 60.71 270 top
PC2596  -  [C0603]  57.61 55.63 90 bottom
PL6  -  [IND_PCMB104TXA]  285.1 104.78 180 bottom
PL8  -  [IND_PCMC063T]  53.19 104.14 0 top
PL9  -  [B2012]  45.92 111.89 180 top
PL11  -  [IND_PCMB104T]  55.73 43.6 180 top
PL12  -  [B2012]  288.49 111.76 180 bottom
PL20  -  [B2012]  55.81 36.62 180 top
PR332  -  [R0402]  300.62 111.27 270 top
PR333  -  [R0402]  300.3 110.75 0 bottom
PR336  -  [R0402]  301.63 101.88 180 bottom
PR339  -  [R0402]  301.51 103.5 0 bottom
PR340  -  [R0603]  299.6 104.02 0 top
PR341  -  [R0603]  297.59 100.72 180 top
PR342  -  [R0402]  301.65 105.83 0 bottom
PR343  -  [R0402]  297.69 104.23 270 top
PR344  -  [R0402]  300.31 105.57 90 top
PR345  -  [R0402]  300.13 101.42 0 top
PR346  -  [R0402]  300.3 108.18 90 bottom
PR347  -  [R0402]  301.65 107.81 0 bottom
PR348  -  [R0603]  303 112.14 90 top
PR357  -  [R0402]  39.09 103.96 0 bottom
PR361  -  [R0402]  40.21 105.08 0 bottom
PR363  -  [R0402]  41.35 103.25 180 top
PR366  -  [R0402]  45.21 104.83 90 bottom
PR367  -  [R0402]  44.04 106.31 270 bottom
PR368  -  [R0402]  42.59 105.26 90 top
PR369  -  [R0603]  43.28 104.58 180 bottom
PR370  -  [R0603]  44.27 102.62 0 bottom
PR371  -  [R0402]  39.7 106.38 180 top
PR372  -  [R0402]  41.53 106.45 90 bottom
PR373  -  [R0402]  42.58 108.74 90 top
PR374  -  [R0402]  41.23 108.36 180 top
PR375  -  [R0603]  60.94 107.82 270 top
PR418  -  [R0402]  71.34 37.04 90 bottom
PR420  -  [R0402]  71.84 47.05 180 top
PR423  -  [R0402]  72 43.62 270 top
PR424  -  [R0603]  70.22 44.82 0 bottom
PR426  -  [R0603]  66.77 48.06 0 bottom
PR427  -  [R0402]  73.84 42.71 0 top
PR428  -  [R0402]  68.34 45.02 90 bottom
PR429  -  [R0402]  68.78 41.91 0 bottom
PR430  -  [R0402]  69.6 47.58 0 bottom
PR431  -  [R0402]  71.02 40.13 270 top
PR432  -  [R0402]  73.46 39.9 270 top
PR433  -  [R0402]  46.86 60.25 0 top
PR434  -  [R0402]  46.86 60.25 0 bottom
PR435  -  [R0402]  46.86 59.23 0 bottom
PR504  -  [R0402]  68.78 43.69 180 bottom
PR505  -  [R0402]  46.86 59.23 0 top
PU17  -  [PQFN17_IR3899]  295.77 105.75 270 bottom
PU19  -  [PQFN16_IR3823]  45.85 106.16 270 top
PU23  -  [PQFN17_IR3895]  66.43 43.01 90 top
Q1  -  [SOT23_GDS]  168.99 110.74 180 top
Q2  -  [SOT23_GDS]  168.99 114.17 180 top
Q3  -  [SOT23_GDS]  296.37 48.84 270 top
Q4  -  [SOT23_GDS]  299.8 48.84 90 top
Q5  -  [SOT23]  315.29 95.5 180 top
Q6  -  [SOT23]  22.07 83.06 0 top
Q7  -  [SOT23_GDS]  305 23.11 90 top
Q15  -  [SOT23_GDS]  293.32 66.8 180 top
Q18  -  [SOT23_GDS]  289.26 66.8 180 top
Q19  -  [SOT23_GDS]  315.29 26.42 270 top
Q20  -  [SOT23_GDS]  298.78 23.11 0 top
Q21  -  [SOT23_GDS]  292.69 26.8 180 top
Q22  -  [SOT23_GDS]  311.1 26.42 270 top
Q23  -  [SOT23_GDS]  292.69 23.11 0 top
Q24  -  [SOT23_GDS]  286.59 26.8 180 top
Q25  -  [SOT23_GDS]  124.79 36.72 90 top
Q26  -  [SOT23_GDS]  124.79 40.92 270 top
Q27  -  [SOT23]  15.11 57.89 0 bottom
R1  -  [R0402]  297.52 53.29 90 top
R2  -  [R0402]  298.53 53.29 270 top
R3  -  [R0402]  296.37 45.79 90 top
R4  -  [R0402]  298.91 51.51 0 top
R5  -  [R0402]  214.71 21.97 0 top
R6  -  [R0402]  296.12 60.02 0 top
R7  -  [R0402]  285.83 83.57 270 top
R8  -  [R0402]  285.83 43.05 270 top
R9  -  [R0402]  278.08 21.97 0 top
R10  -  [R0402]  70.79 68.07 0 top
R11  -  [R0402]  32.21 107.95 90 top
R12  -  [R0402]  29.16 107.95 270 top
R13  -  [R0402]  54.81 94.36 270 top
R14  -  [R0402]  55.96 94.36 270 top
R15  -  [R0402]  60.99 65.85 90 top
R16  -  [R0402]  72.47 68.99 0 top
R17  -  [R0402]  72.47 69.98 0 top
R18  -  [R0402]  72.47 73.72 0 top
R19  -  [R0402]  60.02 84.33 90 top
R20  -  [R0402]  64.92 84.6 90 top
R21  -  [R0402]  305.39 43.56 90 top
R22  -  [R0402]  303.61 43.56 90 top
R23  -  [R0402]  72.34 79.69 0 top
R24  -  [R0402]  72.34 78.68 0 top
R25  -  [R0402]  300.81 43.56 90 top
R26  -  [R0402]  299.16 43.56 90 top
R27  -  [R0402]  300.69 30.99 270 top
R28  -  [R0402]  301.83 30.99 270 top
R29  -  [R0402]  302.85 30.99 270 top
R30  -  [R0402]  303.86 30.99 270 top
R31  -  [R0402]  29.16 105.79 90 top
R32  -  [R0402]  27.89 107.95 270 top
R33  -  [R0402]  34.24 105.79 90 top
R34  -  [R0402]  264.24 21.97 0 top
R35  -  [R0402]  26.87 107.95 90 top
R36  -  [R0402]  63.07 66.1 270 top
R37  -  [R0402]  72.47 71.37 0 top
R38  -  [R0402]  72.47 72.33 0 top
R39  -  [R0402]  274.91 24.89 270 top
R40  -  [R0402]  273.51 25.15 180 top
R41  -  [R0402]  72.34 81.09 0 top
R42  -  [R0402]  73.74 75.49 270 top
R43  -  [R0402]  31.19 107.95 90 top
R44  -  [R0402]  59.89 64.01 270 top
R45  -  [R0402]  59.01 94.36 90 top
R46  -  [R0402]  70.44 64.01 90 top
R47  -  [R0402]  61.04 64.01 90 top
R48  -  [R0402]  57.99 94.36 270 top
R49  -  [R0402]  33.22 105.79 270 top
R50  -  [R0402]  58.88 64.01 90 top
R51  -  [R0402]  30.18 107.95 270 top
R52  -  [R0402]  25.86 105.79 270 top
R53  -  [R0402]  63.07 64.01 90 top
R54  -  [R0402]  57.86 64.01 90 top
R55  -  [R0402]  24.84 107.95 90 top
R56  -  [R0402]  24.84 105.79 270 top
R57  -  [R0402]  62.43 81.15 90 top
R58  -  [R0402]  62.43 82.8 90 top
R59  -  [R0402]  27.89 105.79 90 top
R60  -  [R0402]  76.79 74.42 180 top
R61  -  [R0402]  65.1 67.12 0 top
R62  -  [R0402]  76.79 73.41 180 top
R63  -  [R0402]  75.01 73.41 180 top
R64  -  [R0402]  34.24 107.95 270 top
R65  -  [R0402]  72.34 82.1 0 top
R66  -  [R0402]  63.32 84.58 90 top
R67  -  [R0402]  55.96 92.33 90 top
R68  -  [R0402]  66.42 83.5 90 top
R69  -  [R0402]  33.22 107.95 90 top
R70  -  [R0402]  56.97 92.33 270 top
R71  -  [R0402]  22.81 105.79 90 top
R72  -  [R0402]  55.83 64.01 90 top
R73  -  [R0402]  56.85 64.01 270 top
R74  -  [R0402]  54.81 64.01 90 top
R75  -  [R0402]  65.56 65.72 90 top
R76  -  [R0402]  304.5 62.87 270 top
R77  -  [R0402]  247.35 21.97 0 top
R78  -  [R0402]  307.67 43.56 270 top
R79  -  [R0402]  306.96 28.8 90 top
R80  -  [R0402]  306.96 30.96 90 top
R81  -  [R0402]  308.81 45.85 270 top
R82  -  [R0402]  308.81 43.56 270 top
R83  -  [R0402]  309.96 45.85 270 top
R84  -  [R0402]  309.96 43.56 270 top
R85  -  [R0402]  308.99 28.8 90 top
R86  -  [R0402]  307.98 28.8 90 top
R87  -  [R0402]  307.98 30.96 270 top
R88  -  [R0402]  308.99 30.96 270 top
R89  -  [R0402]  304.5 50.37 90 top
R90  -  [R0402]  305.52 50.37 90 top
R91  -  [R0402]  300.94 51.76 180 top
R92  -  [R0402]  294.98 55.07 90 top
R93  -  [R0402]  69.42 64.01 90 top
R94  -  [R0402]  65.41 64.01 90 top
R95  -  [R0402]  307.67 45.85 270 top
R96  -  [R0402]  306.53 45.85 270 top
R97  -  [R0402]  305.39 45.85 270 top
R98  -  [R0402]  304.24 45.85 270 top
R99  -  [R0402]  303.1 45.85 270 top
R100  -  [R0402]  301.96 45.85 270 top
R101  -  [R0402]  300.81 45.85 270 top
R102  -  [R0402]  299.16 45.85 270 top
R103  -  [R0402]  300.69 28.83 90 top
R104  -  [R0402]  301.83 28.83 90 top
R105  -  [R0402]  302.85 28.83 90 top
R106  -  [R0402]  303.86 28.83 90 top
R107  -  [R0402]  295.96 67.16 270 top
R108  -  [R0402]  66.37 64.01 270 top
R109  -  [R0402]  307.67 24.64 180 top
R110  -  [R0402]  303.86 25.78 180 top
R111  -  [R0402]  68.4 64.01 90 top
R112  -  [R0402]  67.39 64.01 270 top
R113  -  [R0402]  23.83 107.95 270 top
R114  -  [R0402]  23.83 105.79 90 top
R115  -  [R0402]  53.67 94.36 270 top
R116  -  [R0402]  53.67 92.33 270 top
R117  -  [R0402]  56.97 94.36 90 top
R118  -  [R0402]  65.23 89.15 90 top
R119  -  [R0402]  62.18 89.15 90 top
R120  -  [R0402]  67.39 89.15 90 top
R121  -  [R0402]  63.2 89.15 90 top
R122  -  [R0402]  299.79 64.9 90 top
R123  -  [R0402]  298.78 64.9 90 top
R124  -  [R0402]  306.91 60.02 0 top
R125  -  [R0402]  306.91 61.03 0 top
R126  -  [R0402]  302.59 64.9 90 top
R127  -  [R0402]  301.57 64.9 90 top
R128  -  [R0402]  64.21 89.15 90 top
R129  -  [R0402]  65.86 101.09 270 top
R130  -  [R0402]  68.4 89.15 270 top
R131  -  [R0402]  69.42 89.15 270 top
R132  -  [R0402]  54.81 92.33 90 top
R133  -  [R0402]  58.43 84.37 90 top
R134  -  [R0402]  72.34 83.37 0 top
R135  -  [R0402]  263.35 30.86 180 top
R137  -  [R0402]  296.12 57.99 0 top
R141  -  [R0402]  304.93 30.96 270 top
R142  -  [R0402]  305.94 30.96 270 top
R143  -  [R0402]  306.91 57.22 0 top
R144  -  [R0402]  298.53 27.05 90 top
R145  -  [R0402]  299.54 27.05 90 top
R146  -  [R0402]  259.67 26.87 0 top
R147  -  [R0402]  262.46 25.6 90 top
R148  -  [R0402]  259.67 29.92 0 top
R150  -  [R0402]  188.04 75.82 180 top
R151  -  [R0402]  188.04 76.96 180 top
R153  -  [R0402]  288.44 64.54 0 top
R154  -  [R0402]  284.81 43.05 90 top
R155  -  [R0402]  284.81 83.57 90 top
R156  -  [R0402]  294.34 69.09 180 top
R157  -  [R0402]  266.14 29.08 0 top
R158  -  [R0402]  266.14 27.94 0 top
R159  -  [R0402]  290.53 69.09 180 top
R160  -  [R0402]  316.1 29.36 180 top
R161  -  [R0402]  122.12 34.54 0 top
R162  -  [R0402]  295.61 25.27 180 top
R163  -  [R0402]  312.24 29.34 180 top
R164  -  [R0402]  275.92 24.89 90 top
R165  -  [R0402]  278.08 22.99 180 top
R166  -  [R0402]  276.3 21.97 180 top
R183  -  [R0402]  187.95 79.39 180 top
R184  -  [R0402]  187.95 78.25 180 top
R185  -  [R0402]  304.93 28.8 90 top
R186  -  [R0402]  305.94 28.8 90 top
R191  -  [R0402]  125.05 43.56 0 top
R192  -  [R0402]  289.51 25.27 180 top
R193  -  [R0402]  315.16 31.5 270 top
R194  -  [R0402]  122.51 35.94 90 top
R199  -  [R0402]  288.88 83.57 90 top
R200  -  [R0402]  288.88 43.05 90 top
R203  -  [R0402]  296.24 27.56 90 top
R204  -  [R0402]  311.35 31.5 270 top
R209  -  [R0402]  122.51 41.27 270 top
R210  -  [R0402]  290.15 27.56 90 top
R214  -  [R0402]  283.8 83.57 270 top
R215  -  [R0402]  282.78 83.57 270 top
R216  -  [R0402]  283.8 43.05 270 top
R221  -  [R0402]  282.78 43.05 270 top
R226  -  [R0402]  292.18 69.09 0 top
R227  -  [R0402]  288.37 69.09 0 top
R228  -  [R0402]  295.23 27.56 90 top
R233  -  [R0402]  289.13 27.56 90 top
R234  -  [R0402]  122.51 37.72 270 top
R235  -  [R0402]  122.51 39.5 90 top
R236  -  [R0402]  314.15 29.34 0 top
R237  -  [R0402]  310.47 29.34 180 top
R252  -  [R0402]  287.86 83.57 270 top
R257  -  [R0402]  291.54 71.25 90 top
R258  -  [R0402]  290.53 71.25 90 top
R259  -  [R0402]  289.51 71.25 90 top
R260  -  [R0402]  292.56 71.25 90 top
R261  -  [R0402]  287.86 43.05 270 top
R262  -  [R0402]  291.42 30.61 90 top
R263  -  [R0402]  290.4 30.61 90 top
R264  -  [R0402]  289.38 30.61 90 top
R275  -  [R0402]  292.43 30.61 90 top
R276  -  [R0402]  119.08 36.32 270 bottom
R277  -  [R0402]  120.09 40.64 90 bottom
R278  -  [R0402]  119.08 40.64 90 bottom
R279  -  [R0402]  311.35 33.27 270 top
R280  -  [R0402]  312.62 33.27 270 top
R281  -  [R0402]  315.16 45.85 270 top
R282  -  [R0402]  315.16 43.69 270 top
R283  -  [R0402]  313.89 45.85 270 top
R284  -  [R0402]  313.89 43.69 270 top
R285  -  [R0402]  312.62 45.85 270 top
R286  -  [R0402]  312.62 43.69 270 top
R293  -  [R0402]  313.89 31.5 90 top
R294  -  [R0402]  313.89 33.27 90 top
R296  -  [R0402]  120.09 36.32 90 bottom
R297  -  [R0402]  295.1 51.51 0 top
R298  -  [R0402]  297.01 51.51 180 top
R299  -  [R0402]  313.26 78.23 180 bottom
R300  -  [R0402]  313.26 79.12 180 bottom
R301  -  [R0402]  295.86 23.75 0 top
R302  -  [R0402]  307.93 81.15 180 bottom
R303  -  [R0402]  295.23 22.35 270 top
R304  -  [R0402]  289.13 22.35 270 top
R306  -  [R0402]  293.45 11.05 270 top
R307  -  [R0402]  296.24 22.35 270 top
R308  -  [R0402]  290.15 22.35 270 top
R309  -  [R0402]  284.18 56.39 180 top
R310  -  [R0402]  287.1 57.4 0 top
R317  -  [R0402]  280.11 30.61 270 top
R318  -  [R0402]  25.86 107.95 90 top
R338  -  [R0402]  298.53 29.21 270 top
R339  -  [R0402]  299.54 29.21 270 top
R340  -  [R0402]  306.91 58.24 0 top
R341  -  [R0402]  313.26 80.14 180 bottom
R342  -  [R0402]  289.76 23.75 0 top
R347  -  [R0402]  291.67 11.05 270 top
R348  -  [R0402]  166.45 111.12 270 top
R351  -  [R0402]  166.19 114.3 270 top
R352  -  [R0402]  282.91 71.25 270 top
R353  -  [R0402]  282.91 30.61 270 top
R354  -  [R0402]  289 11.05 270 top
R355  -  [R0402]  288.11 11.05 270 top
R356  -  [R0402]  287.22 11.05 270 top
R357  -  [R0402]  289.89 11.05 270 top
R358  -  [R0402]  292.56 11.05 270 top
R359  -  [R0402]  290.78 11.05 270 top
R360  -  [R0402]  284.94 22.35 270 top
R370  -  [R0402]  282.91 22.35 270 top
U1  -  [BGA575_0-8_19-1X21]  62.05 75.56 90 bottom
U2  -  [TSSOP24_P0-65W5-6H1-2]  304.47 37.34 270 top
U3  -  [X2QFN10_0-5_2X1-5]  262.97 29.08 270 top
U4  -  [MSOP8_P0-65H1-1]  307.8 78.74 0 bottom
U5  -  [DELTAL_COUPON_7P]  -14.65 317.93 0 top
U6  -  [SOIC8]  66.24 96.01 90 top
U7  -  [SOIC8]  313.26 38.48 270 top
U8  -  [SC70-5XB]  284.18 58.17 0 top
U9  -  [VFQFPN40_P0-4_EPAD]  300.71 58.7 90 top
U10  -  [MSOP10_P0-5W4-4_3X3]  181.47 78.5 0 top
U11  -  [SC70-5XB]  279.48 27.94 90 top
U12  -  [TSSOP8_D65_1D2]  120.02 38.41 270 top
U13  -  [SC70-5XB]  158.95 114.43 180 top
U16  -  [SC70-5XB]  282.27 68.58 90 top
U17  -  [SC70-5XB]  282.27 27.94 90 top
U19  -  [SC70-5XB]  283.54 85.72 0 top
U20  -  [SC70-5XB]  283.54 45.21 0 top
U25  -  [DELTAL_COUPON_7P]  -7.54 280.67 180 top
U26  -  [DELTAL_COUPON_7P]  -14.78 342.26 180 top
U29  -  [DELTAL_COUPON_7P]  -7.54 256.11 0 top
U30  -  [DELTAL_COUPON_7P]  -14.65 127.51 0 top
U33  -  [DELTAL_COUPON_7P]  -7.8 69.72 0 top
U34  -  [DELTAL_COUPON_7P]  -14.78 166.5 180 top
U37  -  [DELTAL_COUPON_7P]  -7.8 108.71 180 top
U39  -  [DELTAL_COUPON_7P]  -14.78 223.39 0 bottom
U41  -  [DELTAL_COUPON_7P]  -13.82 198.91 180 bottom
U43  -  [DELTAL_COUPON_7P]  -14.78 8.13 180 bottom
U45  -  [DELTAL_COUPON_7P]  -14.91 47.12 0 bottom
U47  -  [SC70-5XB]  276.68 27.94 270 top

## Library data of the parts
C1 C8 C11 C13 C145 C147 C149 C153 C154 C156-C159 C172 C182 C184 C186 C191 C216-C223 C225 C227 C243 C244 C246-C248 C250 C251 C253-C255 C257-C259 C265 C352 C450-C452 C455 C456 C460 C461 C465 PC522 PC532 PC551 PC553 PC592 PC593 = CAP: part number: CAP_0402-0.1UF,CAP-42E000D1-D0,X7R,10%,16V
C2 C4 C6 C9 C15 C19 C133-C141 C143 C151 C161 C163 C386 C390 C394 C398 C402 C406 C410 C414 C418 C422 C426 C430 C434 C438 C442 = CAP: alternate symbols: C0201_BGA; part number: CAP_-0.1UF,CAP-21D000D1-D0,X7R,10%,10V
C3 C12 C127 C160 C183 C185 C187 C188 PC518 = CAP: part number: CAP_0402-0.01UF,CAP-42E00D01-D0,X7R,10%,16V
C5 C7 C10 C14 C16-C18 C20-C22 C53 C54 C128-C132 C142 C144 C146 C148 C150 C162 C164 C181 C194 C269 C271 C273 C275 C277 C279 C281 C283 C287 C290 C294 C297 = CAP: alternate symbols: C0201_BGA; part number: CAP_-0.01UF,CAP-21E00D01-D0,X7R,10%,16V
C23-C46 C55-C126 = CAP: part number: CAP_0402-0.22UF,CAP-42E00D22-D0,X7R,10%,16V
C47 C48 C168 C169 C477-C480 = CAP: part number: CAP_0805-22UF,CAP-85E00022-E0,X6S,20%,16V
C49-C52 C174-C177 = CAP: part number: CAP_0402-4.7UF,CAP-42C004D7-E0,X6S,20%,6.3V
C152 C242 C249 = CAP: part number: CAP_0805-10UF,CAP-85E00010-D0,X6S,10%,16V
C155 C215 C224 C226 C245 C252 = CAP: part number: CAP_0603-10UF,CAP-63C00010-E0,X7T,20%,6.3V
C165-C167 C171 = CAPP: part number: CAPP_-680UF,CAP-PLJ00680-E0,POLCAP,20%,2.5V
C170 C173 = CAPP: part number: CAPP_-680UF,CAP-PLJ00680-E0,EMPTY,20%,2.5V
C178 PC511 PC543 PC584 = CAP: part number: CAP_0402-0.1UF,CAP-42F000D1-D0,X7R,10%,25V
C179 = CAP: part number: CAP_0402-1UF,CAP-42D00001-D1,X7R,10%,10V
C180 C189 C190 = CAP: part number: CAP_0402-0.47UF,CAP-42D00D47-D0,X7R,10%,10V
C192 PC552 PC554 PC556 PC557 PC1592 PC1594 PC1595 PC2596 = CAP: part number: CAP_0603-22UF,CAP-63B00022-E0,X6S,20%,4V
C193 = CAP: part number: CAP_0805-22UF,CAP-85C00022-E0,EMPTY,20%,6.3V
C260 C468 C469 PC527 PC555 PC597 = CAP: part number: CAP_0402-2200PF,CAP-42GD0022-D0,X7R,10%,50V
C463 C464 PC515 PC517 PC519-PC521 PC545 PC548 PC585 PC586 PC588 PC788 PC1588 PC1589 = CAP: part number: CAP_1206-22UF,CAP-C6F00022-E0,X6S,20%,25V
C466 PC550 = CAP: part number: CAP_1206-22UF,CAP-C6F00022-E0,EMPTY,20%,25V
C467 = CAP: part number: CAP_0402-0.1UF,CAP-42E000D1-D0,EMPTY,10%,16V
CON1 = HEADER1X4: part number: HEADER1X4_-HEADER1X4S_P2_RA,COH-004SM200-00,IO,,
D1 = LED_2P: part number: LED_2P_-LTST-C193KGKT-5A,LED-S1SG000V-00,IC,,
H1 MH8 = STANDOFF: part number: STANDOFF_-HOLE_C10D5-6B10_NPB_H11_STANDOFF,TSW-AM3L5P1P-00,EMPTY,,
J1-J3 = PCIE_X16: part number: PCIE_X16_-2EG08213-9ADM-JF,COB-PCE164DV-03,IO,,
J5 = GF_PCIE_X16: part number: GF_PCIE_X16_-GF_PCIE_X16,,,,
J6 = PWR2X6: part number: PWR2X6_-2NH_PWR2X6,COP-012D0003-02,IO,,,
J7 J8 = SLIVER_X8_50P: part number: SLIVER_X8_50P_-2292055-1,COS-SLV050SR-00,IO,,
L1 = BEAD: part number: BEAD_-600,BED-06002012-00,IC,25%,,
L2 = BEAD: part number: BEAD_-330,BED-03302013-00,IC,25%,,
L3-L6 PL9 PL12 PL20 = BEAD: part number: BEAD_-22,BED-00222012-00,IC,25%,,
ME1 = DUMMY_SYMBOL_NO_PIN: part number: DUMMY_SYMBOL_NO_PIN_-LABEL20X4_SST21X5,MEDUMMY5,EMPTY,,
ME4 = DUMMY_SYMBOL_NO_PIN: part number: DUMMY_SYMBOL_NO_PIN_-LABEL_32X6_FULL,MEDUMMY7,EMPTY,,
ME5 = DUMMY_SYMBOL_NO_PIN: part number: DUMMY_SYMBOL_NO_PIN_-ZT_LOG_6X16,MEDUMMY3,EMPTY,,
MH1-MH4 = GRD_HOLE: part number: GRD_HOLE_-HOLE_D3N_PKO10,GRD_HOLE4,EMPTY
MH5-MH7 MH9-MH11 = SCREW_NP_5VIA: part number: SCREW_NP_5VIA_-C10D4XC10D6.5_5V,TEMP_C10D4XC10D6.5_L5,EMPTY,,
PC506 = CAP: part number: CAP_0402-0.01UF,CAP-42G00D01-D0,X7R,10%,50V
PC508 PC541 PC581 = CAP: part number: CAP_0603-2.2UF,CAP-63D002D2-D0,X7R,10%,10V
PC509 PC582 = CAP: part number: CAP_0402-100PF,CAP-42GD0001-C0,NP0,5%,50V
PC510 PC542 PC583 = CAP: part number: CAP_0603-1UF,CAP-63F00001-D0,X7R,10%,25V
PC514 PC546 PC587 = CAP: part number: CAP_0603-0.1UF,CAP-63G000D1-D0,X7R,10%,50V
PC516 PC589 = CAP: part number: CAP_0402-150PF,CAP-42G0150P-C0,NP0,5%,50V
PC524 PC526 PC529-PC531 PC533 PC1531 PC1533 = CAP: part number: CAP_0805-22UF,CAP-85C00022-E0,X6S,20%,6.3V
PC539 PC580 = CAP: part number: CAP_0402-1000PF,CAP-42G0D001-D0,X7R,10%,50V
PC547 = CAP: part number: CAP_0402-33PF,CAP-42G0033P-C0,NP0,5%,50V
PC549 PC591 = CAP: part number: CAP_0402-6800PF,CAP-42FD0068-D0,X7R,10%,25V
PC594-PC596 PC598-PC600 PC1596 PC1598-PC1600 = CAP: part number: CAP_0805-47UF,CAP-85B00047-E0,X6S,20%,4V
PL6 = INDUCTOR: part number: INDUCTOR_-2.2UH,IND-C104T2R2-M0,IC,20%,12A,
PL8 = INDUCTOR: part number: INDUCTOR_-4.7UH,IND-C063T4R7-M0,IC,20%,5.5A,
PL11 = INDUCTOR: part number: INDUCTOR_-0.36UH,IND-C104TR36-M0,IC,20%,30A,
PR332 = RES: part number: RES_0402-47K,RES-4200047K-B0,IC,1%,1/16W
PR333 = RES: part number: RES_0402-6.98K,RES-4206D98K-B0,IC,1%,1/16W
PR336 PR363 PR420 R1-R4 R6 R95-R106 R137 R144 R145 R150 R151 R156 R159 R185 R186 R193 R194 R203 R204 R209 R210 R303 R304 R341 R348 = RES: part number: RES_0402-4.7K,RES-42004D7K-B0,IC,1%,1/16W
PR339 PR423 = RES: part number: RES_0402-39.2K,RES-42039D2K-B0,IC,1%,1/16W
PR340 PR341 PR348 PR369 PR370 PR375 PR424 PR426 = RES: part number: RES_0603-0,RES-63000000-C0,IC,5%,1A
PR342 = RES: part number: RES_0402-5.6K,RES-42005D6K-B0,IC,1%,1/16W
PR343 PR344 R277 R278 = RES: part number: RES_0402-2.2K,RES-42002D2K-B0,IC,1%,1/16W
PR345 PR347 PR428 PR429 = RES: part number: RES_0402-12.4K,RES-42012D4K-B0,IC,1%,1/16W
PR346 PR373 PR431 = RES: part number: RES_0402-120,RES-42000120-B0,IC,1%,1/16W
PR357 PR366 PR418 PR434 PR435 R5 R7 R8 R21 R22 R25-R30 R34 R40 R77 R85 R86 R89 R90 R118 R119 R130 R131 R135 R141 R142 R157 R158 R165 R215 R221 R276 R298 R306 R338 R339 R347 R354 R355 R370 = RES: part number: RES_0402-0,RES-42000000-C0,IC,5%,1A
PR361 = RES: part number: RES_0402-6.34K,RES-4206D34K-B0,EMPTY,1%,1/16W
PR367 R9 R39 R44 R45 R166 R214 R216 R226-R228 R233-R237 R297 R307 R308 R358 = RES: part number: RES_0402-0,RES-42000000-C0,EMPTY,5%,1A
PR368 = RES: part number: RES_0402-36.5K,RES-42036D5K-B0,IC,1%,1/16W
PR371 PR372 = RES: part number: RES_0402-4.99K,RES-4204D99K-F0,IC,0.1%,1/16W
PR374 PR430 R120 R129 R154 R155 R164 R283 R285 R302 = RES: part number: RES_0402-10K,RES-4200010K-B0,IC,1%,1/16W
PR427 = RES: part number: RES_0402-6.19K,RES-4206D19K-B0,IC,1%,1/16W
PR432 = RES: part number: RES_0402-10.2K,RES-42010D2K-B0,IC,1%,1/16W
PR433 PR505 R59 R61 R65-R68 R71 R76 R107 R108 R112 R146-R148 R153 R160-R163 R191 R192 R199 R200 R282 R294 R301 R318 R342 = RES: part number: RES_0402-100,RES-42000100-B0,IC,1%,1/16W
PR504 = RES: part number: RES_0402-10,RES-42000010-B0,IC,1%,1/16W
PU17 = IR3899: part number: IR3899_-IR3899MTPRPBF,ICP-IR3899MT-00,IC,,
PU19 = IR3823_1: part number: IR3823_1_-IR3823MTRPBF,ICP-IR3823MT-00,IC,,,
PU23 = IR3895: part number: IR3895_-IR3895MTPRPBF,ICP-IR3895MT-00,IC,,
Q1-Q4 Q7 Q15 Q18-Q26 = 2N7002: part number: 2N7002_-2N7002,MOS-002N7002-00,IC,,,
Q5 Q6 Q27 = NPN: part number: NPN_-MMBT3904LT1G,BJT-MMBT3904-00,IC,,,
R10 = RES: part number: RES_0402-1.5K,RES-42001D5K-B0,IC,1%,1/16W
R11-R20 R23 R24 R31-R33 R35-R38 R41-R43 R132-R134 = RES: part number: RES_0402-3K,RES-4200003K-B0,IC,1%,1/16W
R46-R56 R87 R88 R252 R257-R264 R275 R296 R317 R352 R353 R356 R357 R359 = RES: part number: RES_0402-4.7K,RES-42004D7K-B0,EMPTY,1%,1/16W
R57 R60 R62 R70 R72 R74 R93 R94 R111 = RES: part number: RES_0402-1K,RES-4200001K-B0,EMPTY,1%,1/16W
R58 R63 R73 R75 R114 R116 R284 R286 = RES: part number: RES_0402-100,RES-42000100-B0,EMPTY,1%,1/16W
R64 R69 R113 R115 R117 R121 R128 R351 = RES: part number: RES_0402-1K,RES-4200001K-B0,IC,1%,1/16W
R78 R81 = RES: part number: RES_0402-8.2K,RES-42008D2K-B0,IC,1%,1/16W
R79 R83 = RES: part number: RES_0402-8.2K,RES-42008D2K-B0,EMPTY,1%,1/16W
R80 R84 = RES: part number: RES_0402-475,RES-42000475-B0,IC,1%,1/16W
R82 = RES: part number: RES_0402-475,RES-42000475-B0,EMPTY,1%,1/16W
R91 R92 = RES: part number: RES_0402-2.2,RES-420002D2-B0,IC,1%,1/16W
R109 R281 R293 R360 = RES: part number: RES_0402-10K,RES-4200010K-B0,EMPTY,1%,1/16W
R110 = RES: part number: RES_0402-300,RES-42000300-B0,IC,1%,1/16W
R122-R127 R143 R340 = RES: part number: RES_0402-27.4,RES-420027D4-B0,IC,1%,1/16W
R183 R184 R279 R280 R299 R300 = RES: part number: RES_0402-22,RES-42000022-B0,IC,1%,1/16W
R309 = RES: part number: RES_0402-100K,RES-4200100K-B0,IC,1%,1/16W
R310 = RES: part number: RES_0402-100K,RES-4200100K-B0,EMPTY,1%,1/16W
U1 = PEX8747CA80FBCG: part number: PEX8747CA80FBCG_-PEX8747-CA80FBC_G,ICC-PEX8747C-00,IC,,
U2 = PCA9548: part number: PCA9548_-PCA9548APW,ICC-PCA9548A-00,IC,,
U3 = TLA2024IRUGR: part number: TLA2024IRUGR_-TLA2024IRUGR,ICC-TLA2024I-00,IC,,
U4 = EMC1412: part number: EMC1412_-EMC1412-1-ACZL-TR,ICC-EMC14121-00,IC,,
U5 U25 U26 U29 U30 U33 U34 U37 U39 U41 U43 U45 = COUPON_7P: part number: COUPON_7P_-COUPON,,EMPTY,,
U6 = AT25256B: part number: AT25256B_-AT25256B-SSHL-T,ICM-AT25256B-00,IC,,
U7 = AT24C64D: part number: AT24C64D_-AT24C64D-SSHM-T,ICM-AT24C64D-00,IC,,
U8 U11 U16 U17 = SN74LVC1G17: part number: SN74LVC1G17_-SN74LVC1G17DCKR,ICC-LVC1G17D-00,IC,,,
U9 = 9ZXL0651AKLFT: part number: 9ZXL0651AKLFT_-9ZXL0651AKLFT,ICC-9ZXL0651-00,IC,,
U10 = EMC1413AAIZLTR: part number: EMC1413AAIZLTR_-EMC1413-A-AIZL-TR,ICC-EMC1413A-00,IC,,
U12 = PCA9617: part number: PCA9617_-PCA9617ADP,ICC-PCA9617A-00,IC,,
U13 = SN74AUP1T17DCKR: part number: SN74AUP1T17DCKR_-SN74AUP1T17DCKR,ICC-74AUP1T1-00,IC,,
U19 U20 U47 = SN74LVC1G07: part number: SN74LVC1G07_-SN74LVC1G07DCKR,ICC-LVC1G07D-00,IC,,,

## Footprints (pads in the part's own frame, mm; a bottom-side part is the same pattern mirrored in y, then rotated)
B2012
  rect 1.118x1.372 smd: 1(-0.95,0) 2(0.95,0)
BGA575_0-8_19-1X21
  round 0.406 smd: A1(-8.8,9.6) A2(-8,9.6) A3(-7.2,9.6) A4(-6.4,9.6) A5(-5.6,9.6) A6(-4.8,9.6) A7(-4,9.6) A8(-3.2,9.6) A9(-2.4,9.6) A10(-1.6,9.6) A11(-0.8,9.6) A12(0,9.6) A13(0.8,9.6) A14(1.6,9.6) A15(2.4,9.6) A16(3.2,9.6) A17(4,9.6) A18(4.8,9.6) A19(5.6,9.6) A20(6.4,9.6) A21(7.2,9.6) A22(8,9.6) A23(8.8,9.6) AA1(-8.8,-6.4) AA2(-8,-6.4) AA3(-7.2,-6.4) AA4(-6.4,-6.4) AA5(-5.6,-6.4) AA6(-4.8,-6.4) AA7(-4,-6.4) AA8(-3.2,-6.4) AA9(-2.4,-6.4) AA10(-1.6,-6.4) AA11(-0.8,-6.4) AA12(0,-6.4) AA13(0.8,-6.4) AA14(1.6,-6.4) AA15(2.4,-6.4) AA16(3.2,-6.4) AA17(4,-6.4) AA18(4.8,-6.4) AA19(5.6,-6.4) AA20(6.4,-6.4) AA21(7.2,-6.4) AA22(8,-6.4) AA23(8.8,-6.4) AB1(-8.8,-7.2) AB2(-8,-7.2) AB3(-7.2,-7.2) AB4(-6.4,-7.2) AB5(-5.6,-7.2) AB6(-4.8,-7.2) AB7(-4,-7.2) AB8(-3.2,-7.2) AB9(-2.4,-7.2) AB10(-1.6,-7.2) AB11(-0.8,-7.2) AB12(0,-7.2) AB13(0.8,-7.2) AB14(1.6,-7.2) AB15(2.4,-7.2) AB16(3.2,-7.2) AB17(4,-7.2) AB18(4.8,-7.2) AB19(5.6,-7.2) AB20(6.4,-7.2) AB21(7.2,-7.2) AB22(8,-7.2) AB23(8.8,-7.2) AC1(-8.8,-8) AC2(-8,-8) AC3(-7.2,-8) AC4(-6.4,-8) AC5(-5.6,-8) AC6(-4.8,-8) AC7(-4,-8) AC8(-3.2,-8) AC9(-2.4,-8) AC10(-1.6,-8) AC11(-0.8,-8) AC12(0,-8) AC13(0.8,-8) AC14(1.6,-8) AC15(2.4,-8) AC16(3.2,-8) AC17(4,-8) AC18(4.8,-8) AC19(5.6,-8) AC20(6.4,-8) AC21(7.2,-8) AC22(8,-8) AC23(8.8,-8) AD1(-8.8,-8.8) AD2(-8,-8.8) AD3(-7.2,-8.8) AD4(-6.4,-8.8) AD5(-5.6,-8.8) AD6(-4.8,-8.8) AD7(-4,-8.8) AD8(-3.2,-8.8) AD9(-2.4,-8.8) AD10(-1.6,-8.8) AD11(-0.8,-8.8) AD12(0,-8.8) AD13(0.8,-8.8) AD14(1.6,-8.8) AD15(2.4,-8.8) AD16(3.2,-8.8) AD17(4,-8.8) AD18(4.8,-8.8) AD19(5.6,-8.8) AD20(6.4,-8.8) AD21(7.2,-8.8) AD22(8,-8.8) AD23(8.8,-8.8) AE1(-8.8,-9.6) AE2(-8,-9.6) AE3(-7.2,-9.6) AE4(-6.4,-9.6) AE5(-5.6,-9.6) AE6(-4.8,-9.6) AE7(-4,-9.6) AE8(-3.2,-9.6) AE9(-2.4,-9.6) AE10(-1.6,-9.6) AE11(-0.8,-9.6) AE12(0,-9.6) AE13(0.8,-9.6) AE14(1.6,-9.6) AE15(2.4,-9.6) AE16(3.2,-9.6) AE17(4,-9.6) AE18(4.8,-9.6) AE19(5.6,-9.6) AE20(6.4,-9.6) AE21(7.2,-9.6) AE22(8,-9.6) AE23(8.8,-9.6) B1(-8.8,8.8) B2(-8,8.8) B3(-7.2,8.8) B4(-6.4,8.8) B5(-5.6,8.8) B6(-4.8,8.8) B7(-4,8.8) B8(-3.2,8.8) B9(-2.4,8.8) B10(-1.6,8.8) B11(-0.8,8.8) B12(0,8.8) B13(0.8,8.8) B14(1.6,8.8) B15(2.4,8.8) B16(3.2,8.8) B17(4,8.8) B18(4.8,8.8) B19(5.6,8.8) B20(6.4,8.8) B21(7.2,8.8) B22(8,8.8) B23(8.8,8.8) C1(-8.8,8) C2(-8,8) C3(-7.2,8) C4(-6.4,8) C5(-5.6,8) C6(-4.8,8) C7(-4,8) C8(-3.2,8) C9(-2.4,8) C10(-1.6,8) C11(-0.8,8) C12(0,8) C13(0.8,8) C14(1.6,8) C15(2.4,8) C16(3.2,8) C17(4,8) C18(4.8,8) C19(5.6,8) C20(6.4,8) C21(7.2,8) C22(8,8) C23(8.8,8) D1(-8.8,7.2) D2(-8,7.2) D3(-7.2,7.2) D4(-6.4,7.2) D5(-5.6,7.2) D6(-4.8,7.2) D7(-4,7.2) D8(-3.2,7.2) D9(-2.4,7.2) D10(-1.6,7.2) D11(-0.8,7.2) D12(0,7.2) D13(0.8,7.2) D14(1.6,7.2) D15(2.4,7.2) D16(3.2,7.2) D17(4,7.2) D18(4.8,7.2) D19(5.6,7.2) D20(6.4,7.2) D21(7.2,7.2) D22(8,7.2) D23(8.8,7.2) E1(-8.8,6.4) E2(-8,6.4) E3(-7.2,6.4) E4(-6.4,6.4) E5(-5.6,6.4) E6(-4.8,6.4) E7(-4,6.4) E8(-3.2,6.4) E9(-2.4,6.4) E10(-1.6,6.4) E11(-0.8,6.4) E12(0,6.4) E13(0.8,6.4) E14(1.6,6.4) E15(2.4,6.4) E16(3.2,6.4) E17(4,6.4) E18(4.8,6.4) E19(5.6,6.4) E20(6.4,6.4) E21(7.2,6.4) E22(8,6.4) E23(8.8,6.4) F1(-8.8,5.6) F2(-8,5.6) F3(-7.2,5.6) F4(-6.4,5.6) F5(-5.6,5.6) F6(-4.8,5.6) F7(-4,5.6) F8(-3.2,5.6) F9(-2.4,5.6) F10(-1.6,5.6) F11(-0.8,5.6) F12(0,5.6) F13(0.8,5.6) F14(1.6,5.6) F15(2.4,5.6) F16(3.2,5.6) F17(4,5.6) F18(4.8,5.6) F19(5.6,5.6) F20(6.4,5.6) F21(7.2,5.6) F22(8,5.6) F23(8.8,5.6) G1(-8.8,4.8) G2(-8,4.8) G3(-7.2,4.8) G4(-6.4,4.8) G5(-5.6,4.8) G6(-4.8,4.8) G7(-4,4.8) G8(-3.2,4.8) G9(-2.4,4.8) G10(-1.6,4.8) G11(-0.8,4.8) G12(0,4.8) G13(0.8,4.8) G14(1.6,4.8) G15(2.4,4.8) G16(3.2,4.8) G17(4,4.8) G18(4.8,4.8) G19(5.6,4.8) G20(6.4,4.8) G21(7.2,4.8) G22(8,4.8) G23(8.8,4.8) H1(-8.8,4) H2(-8,4) H3(-7.2,4) H4(-6.4,4) H5(-5.6,4) H6(-4.8,4) H7(-4,4) H8(-3.2,4) H9(-2.4,4) H10(-1.6,4) H11(-0.8,4) H12(0,4) H13(0.8,4) H14(1.6,4) H15(2.4,4) H16(3.2,4) H17(4,4) H18(4.8,4) H19(5.6,4) H20(6.4,4) H21(7.2,4) H22(8,4) H23(8.8,4) J1(-8.8,3.2) J2(-8,3.2) J3(-7.2,3.2) J4(-6.4,3.2) J5(-5.6,3.2) J6(-4.8,3.2) J7(-4,3.2) J8(-3.2,3.2) J9(-2.4,3.2) J10(-1.6,3.2) J11(-0.8,3.2) J12(0,3.2) J13(0.8,3.2) J14(1.6,3.2) J15(2.4,3.2) J16(3.2,3.2) J17(4,3.2) J18(4.8,3.2) J19(5.6,3.2) J20(6.4,3.2) J21(7.2,3.2) J22(8,3.2) J23(8.8,3.2) K1(-8.8,2.4) K2(-8,2.4) K3(-7.2,2.4) K4(-6.4,2.4) K5(-5.6,2.4) K6(-4.8,2.4) K7(-4,2.4) K8(-3.2,2.4) K9(-2.4,2.4) K10(-1.6,2.4) K11(-0.8,2.4) K12(0,2.4) K13(0.8,2.4) K14(1.6,2.4) K15(2.4,2.4) K16(3.2,2.4) K17(4,2.4) K18(4.8,2.4) K19(5.6,2.4) K20(6.4,2.4) K21(7.2,2.4) K22(8,2.4) K23(8.8,2.4) L1(-8.8,1.6) L2(-8,1.6) L3(-7.2,1.6) L4(-6.4,1.6) L5(-5.6,1.6) L6(-4.8,1.6) L7(-4,1.6) L8(-3.2,1.6) L9(-2.4,1.6) L10(-1.6,1.6) L11(-0.8,1.6) L12(0,1.6) L13(0.8,1.6) L14(1.6,1.6) L15(2.4,1.6) L16(3.2,1.6) L17(4,1.6) L18(4.8,1.6) L19(5.6,1.6) L20(6.4,1.6) L21(7.2,1.6) L22(8,1.6) L23(8.8,1.6) M1(-8.8,0.8) M2(-8,0.8) M3(-7.2,0.8) M4(-6.4,0.8) M5(-5.6,0.8) M6(-4.8,0.8) M7(-4,0.8) M8(-3.2,0.8) M9(-2.4,0.8) M10(-1.6,0.8) M11(-0.8,0.8) M12(0,0.8) M13(0.8,0.8) M14(1.6,0.8) M15(2.4,0.8) M16(3.2,0.8) M17(4,0.8) M18(4.8,0.8) M19(5.6,0.8) M20(6.4,0.8) M21(7.2,0.8) M22(8,0.8) M23(8.8,0.8) N1(-8.8,0) N2(-8,0) N3(-7.2,0) N4(-6.4,0) N5(-5.6,0) N6(-4.8,0) N7(-4,0) N8(-3.2,0) N9(-2.4,0) N10(-1.6,0) N11(-0.8,0) N12(0,0) N13(0.8,0) N14(1.6,0) N15(2.4,0) N16(3.2,0) N17(4,0) N18(4.8,0) N19(5.6,0) N20(6.4,0) N21(7.2,0) N22(8,0) N23(8.8,0) P1(-8.8,-0.8) P2(-8,-0.8) P3(-7.2,-0.8) P4(-6.4,-0.8) P5(-5.6,-0.8) P6(-4.8,-0.8) P7(-4,-0.8) P8(-3.2,-0.8) P9(-2.4,-0.8) P10(-1.6,-0.8) P11(-0.8,-0.8) P12(0,-0.8) P13(0.8,-0.8) P14(1.6,-0.8) P15(2.4,-0.8) P16(3.2,-0.8) P17(4,-0.8) P18(4.8,-0.8) P19(5.6,-0.8) P20(6.4,-0.8) P21(7.2,-0.8) P22(8,-0.8) P23(8.8,-0.8) R1(-8.8,-1.6) R2(-8,-1.6) R3(-7.2,-1.6) R4(-6.4,-1.6) R5(-5.6,-1.6) R6(-4.8,-1.6) R7(-4,-1.6) R8(-3.2,-1.6) R9(-2.4,-1.6) R10(-1.6,-1.6) R11(-0.8,-1.6) R12(0,-1.6) R13(0.8,-1.6) R14(1.6,-1.6) R15(2.4,-1.6) R16(3.2,-1.6) R17(4,-1.6) R18(4.8,-1.6) R19(5.6,-1.6) R20(6.4,-1.6) R21(7.2,-1.6) R22(8,-1.6) R23(8.8,-1.6) T1(-8.8,-2.4) T2(-8,-2.4) T3(-7.2,-2.4) T4(-6.4,-2.4) T5(-5.6,-2.4) T6(-4.8,-2.4) T7(-4,-2.4) T8(-3.2,-2.4) T9(-2.4,-2.4) T10(-1.6,-2.4) T11(-0.8,-2.4) T12(0,-2.4) T13(0.8,-2.4) T14(1.6,-2.4) T15(2.4,-2.4) T16(3.2,-2.4) T17(4,-2.4) T18(4.8,-2.4) T19(5.6,-2.4) T20(6.4,-2.4) T21(7.2,-2.4) T22(8,-2.4) T23(8.8,-2.4) U1(-8.8,-3.2) U2(-8,-3.2) U3(-7.2,-3.2) U4(-6.4,-3.2) U5(-5.6,-3.2) U6(-4.8,-3.2) U7(-4,-3.2) U8(-3.2,-3.2) U9(-2.4,-3.2) U10(-1.6,-3.2) U11(-0.8,-3.2) U12(0,-3.2) U13(0.8,-3.2) U14(1.6,-3.2) U15(2.4,-3.2) U16(3.2,-3.2) U17(4,-3.2) U18(4.8,-3.2) U19(5.6,-3.2) U20(6.4,-3.2) U21(7.2,-3.2) U22(8,-3.2) U23(8.8,-3.2) V1(-8.8,-4) V2(-8,-4) V3(-7.2,-4) V4(-6.4,-4) V5(-5.6,-4) V6(-4.8,-4) V7(-4,-4) V8(-3.2,-4) V9(-2.4,-4) V10(-1.6,-4) V11(-0.8,-4) V12(0,-4) V13(0.8,-4) V14(1.6,-4) V15(2.4,-4) V16(3.2,-4) V17(4,-4) V18(4.8,-4) V19(5.6,-4) V20(6.4,-4) V21(7.2,-4) V22(8,-4) V23(8.8,-4) W1(-8.8,-4.8) W2(-8,-4.8) W3(-7.2,-4.8) W4(-6.4,-4.8) W5(-5.6,-4.8) W6(-4.8,-4.8) W7(-4,-4.8) W8(-3.2,-4.8) W9(-2.4,-4.8) W10(-1.6,-4.8) W11(-0.8,-4.8) W12(0,-4.8) W13(0.8,-4.8) W14(1.6,-4.8) W15(2.4,-4.8) W16(3.2,-4.8) W17(4,-4.8) W18(4.8,-4.8) W19(5.6,-4.8) W20(6.4,-4.8) W21(7.2,-4.8) W22(8,-4.8) W23(8.8,-4.8) Y1(-8.8,-5.6) Y2(-8,-5.6) Y3(-7.2,-5.6) Y4(-6.4,-5.6) Y5(-5.6,-5.6) Y6(-4.8,-5.6) Y7(-4,-5.6) Y8(-3.2,-5.6) Y9(-2.4,-5.6) Y10(-1.6,-5.6) Y11(-0.8,-5.6) Y12(0,-5.6) Y13(0.8,-5.6) Y14(1.6,-5.6) Y15(2.4,-5.6) Y16(3.2,-5.6) Y17(4,-5.6) Y18(4.8,-5.6) Y19(5.6,-5.6) Y20(6.4,-5.6) Y21(7.2,-5.6) Y22(8,-5.6) Y23(8.8,-5.6)
